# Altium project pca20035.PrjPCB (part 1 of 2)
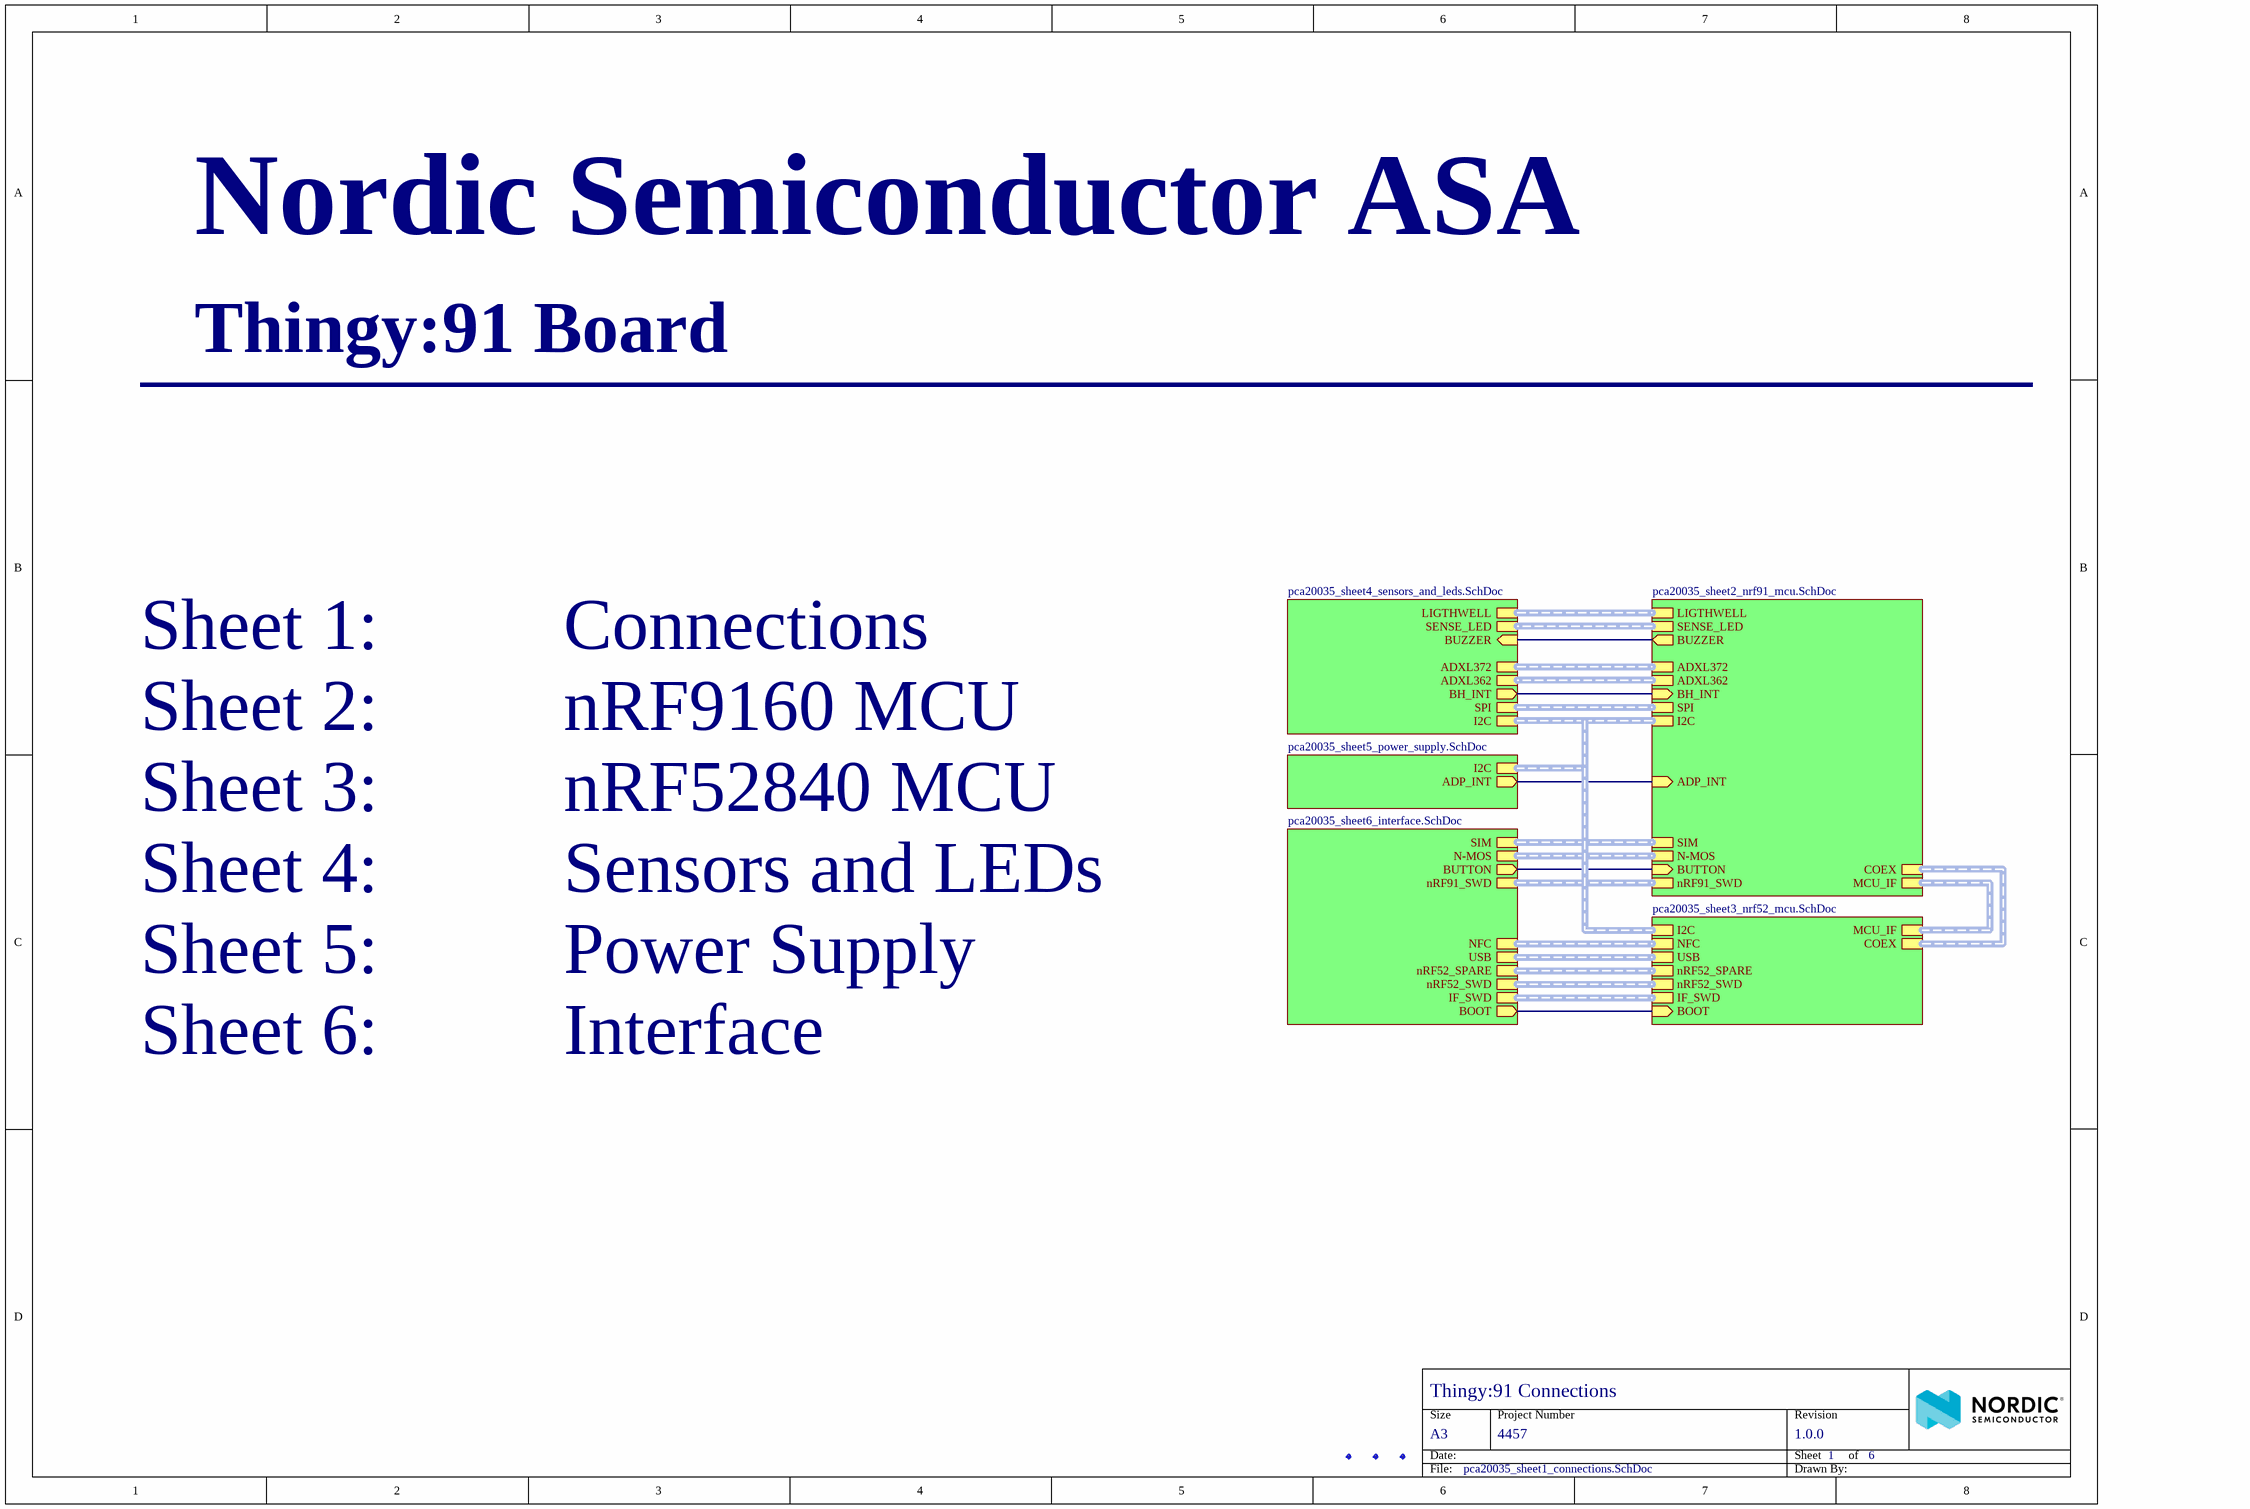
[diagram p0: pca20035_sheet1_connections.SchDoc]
Author: RUBR; BoardThickness: 1.6mm; BoardTitle: Thingy:91 Board; NrOfLayers: 4; Organization: Nordic Semiconductor; PCAName: PCA20035; PCBNumber: 400390; PCBRevision: 0347RUBR; PCBStackup: 4001; ProjectName: nRF91 Thingy; ProjectNumber: 4457; Revision: 1.0.0; SilkscreenColor: White; SoldermaskColor: Blue; SurfaceFinish: ENIG Gold
6 sheets, 236 parts. Net scope: hierarchical (ports join the sheet entries above them; power ports are global).
Board file: 400390.PcbDoc
Sheets:
  pca20035_sheet1_connections.SchDoc
     = pca20035_sheet2_nrf91_mcu.SchDoc
     = pca20035_sheet4_sensors_and_leds.SchDoc
     = pca20035_sheet3_nrf52_mcu.SchDoc
     = pca20035_sheet6_interface.SchDoc
     = pca20035_sheet5_power_supply.SchDoc

## Sheet pca20035_sheet1_connections.SchDoc: Thingy:91 Connections
size A3; Organization: Nordic Semiconductor; DocumentNumber: 1; Revision: 1.0.0; SheetNumber: 1; SheetTotal: 6; Author: RUBR; CompanyName: Nordic Semiconductor; DrawnBy: RUBR; DocumentSize: A3

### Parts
Fid1  Fiducial mark  [Fiducial_Round-Square]  (value not drawn)
Fid2  Fiducial mark  [Fiducial_Round-Square]  (value not drawn)
Fid3  Fiducial mark  [Fiducial_Round-Square]  (value not drawn)

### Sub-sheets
? = pca20035_sheet2_nrf91_mcu.SchDoc: SIM (harness SIM), nRF91_SWD (harness SWD), ADP_INT (in), COEX (harness COEX), BUZZER (out), BH_INT (in), LIGTHWELL (harness LED), MCU_IF (harness MCU_IF), I2C (harness I2C), BUTTON (in), SENSE_LED (harness LED), N-MOS (harness N-MOS), SPI (harness SPI), ADXL372 (harness ADXL), ADXL362 (harness ADXL)
? = pca20035_sheet4_sensors_and_leds.SchDoc: BUZZER (in), I2C (harness I2C), BH_INT (out), LIGTHWELL (harness LED), SENSE_LED (harness LED), SPI (harness SPI), ADXL362 (harness ADXL), ADXL372 (harness ADXL)
? = pca20035_sheet3_nrf52_mcu.SchDoc: USB (harness USB), nRF52_SPARE (harness SPARE), NFC (harness NFC), COEX (harness COEX), IF_SWD (harness IF SWD), I2C (harness I2C), MCU_IF (harness MCU_IF), nRF52_SWD (harness SWD), BOOT (in)
? = pca20035_sheet6_interface.SchDoc: N-MOS (harness N-MOS), NFC (harness NFC), nRF52_SPARE (harness SPARE), SIM (harness SIM), IF_SWD (harness IF SWD), nRF52_SWD (harness SWD), nRF91_SWD (harness SWD), BUTTON (out), USB (harness USB), BOOT (out)
? = pca20035_sheet5_power_supply.SchDoc: I2C (harness I2C), ADP_INT (out)

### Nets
nRF52_P1.13: sheet /BOOT, sheet /BOOT
P0.17/AIN4: sheet /ADP_INT, sheet /ADP_INT
P0.26: sheet /BUTTON, sheet /BUTTON
P0.27: sheet /BH_INT, sheet /BH_INT
P0.28: sheet /BUZZER, sheet /BUZZER

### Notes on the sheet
- Nordic Semiconductor ASA
- ___________________________________________
- Sheet 1:          Connections
- Sheet 2:          nRF9160 MCU
- Sheet 3:          nRF52840 MCU
- Sheet 4:          Sensors and LEDs
- Sheet 5:          Power Supply
- Sheet 6:          Interface

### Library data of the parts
Fid1-Fid3 = Fid-Mark-Round-Square: Artikkelnr Noca: N.A.

## Sheet pca20035_sheet2_nrf91_mcu.SchDoc: Thingy:91 nRF9160 MCU
size A3; Organization: Nordic Semiconductor; DocumentNumber: 2; Revision: 1.0.0; SheetNumber: 2; SheetTotal: 6; Author: RUBR; CompanyName: Nordic Semiconductor; DrawnBy: RUBR; DocumentSize: A3
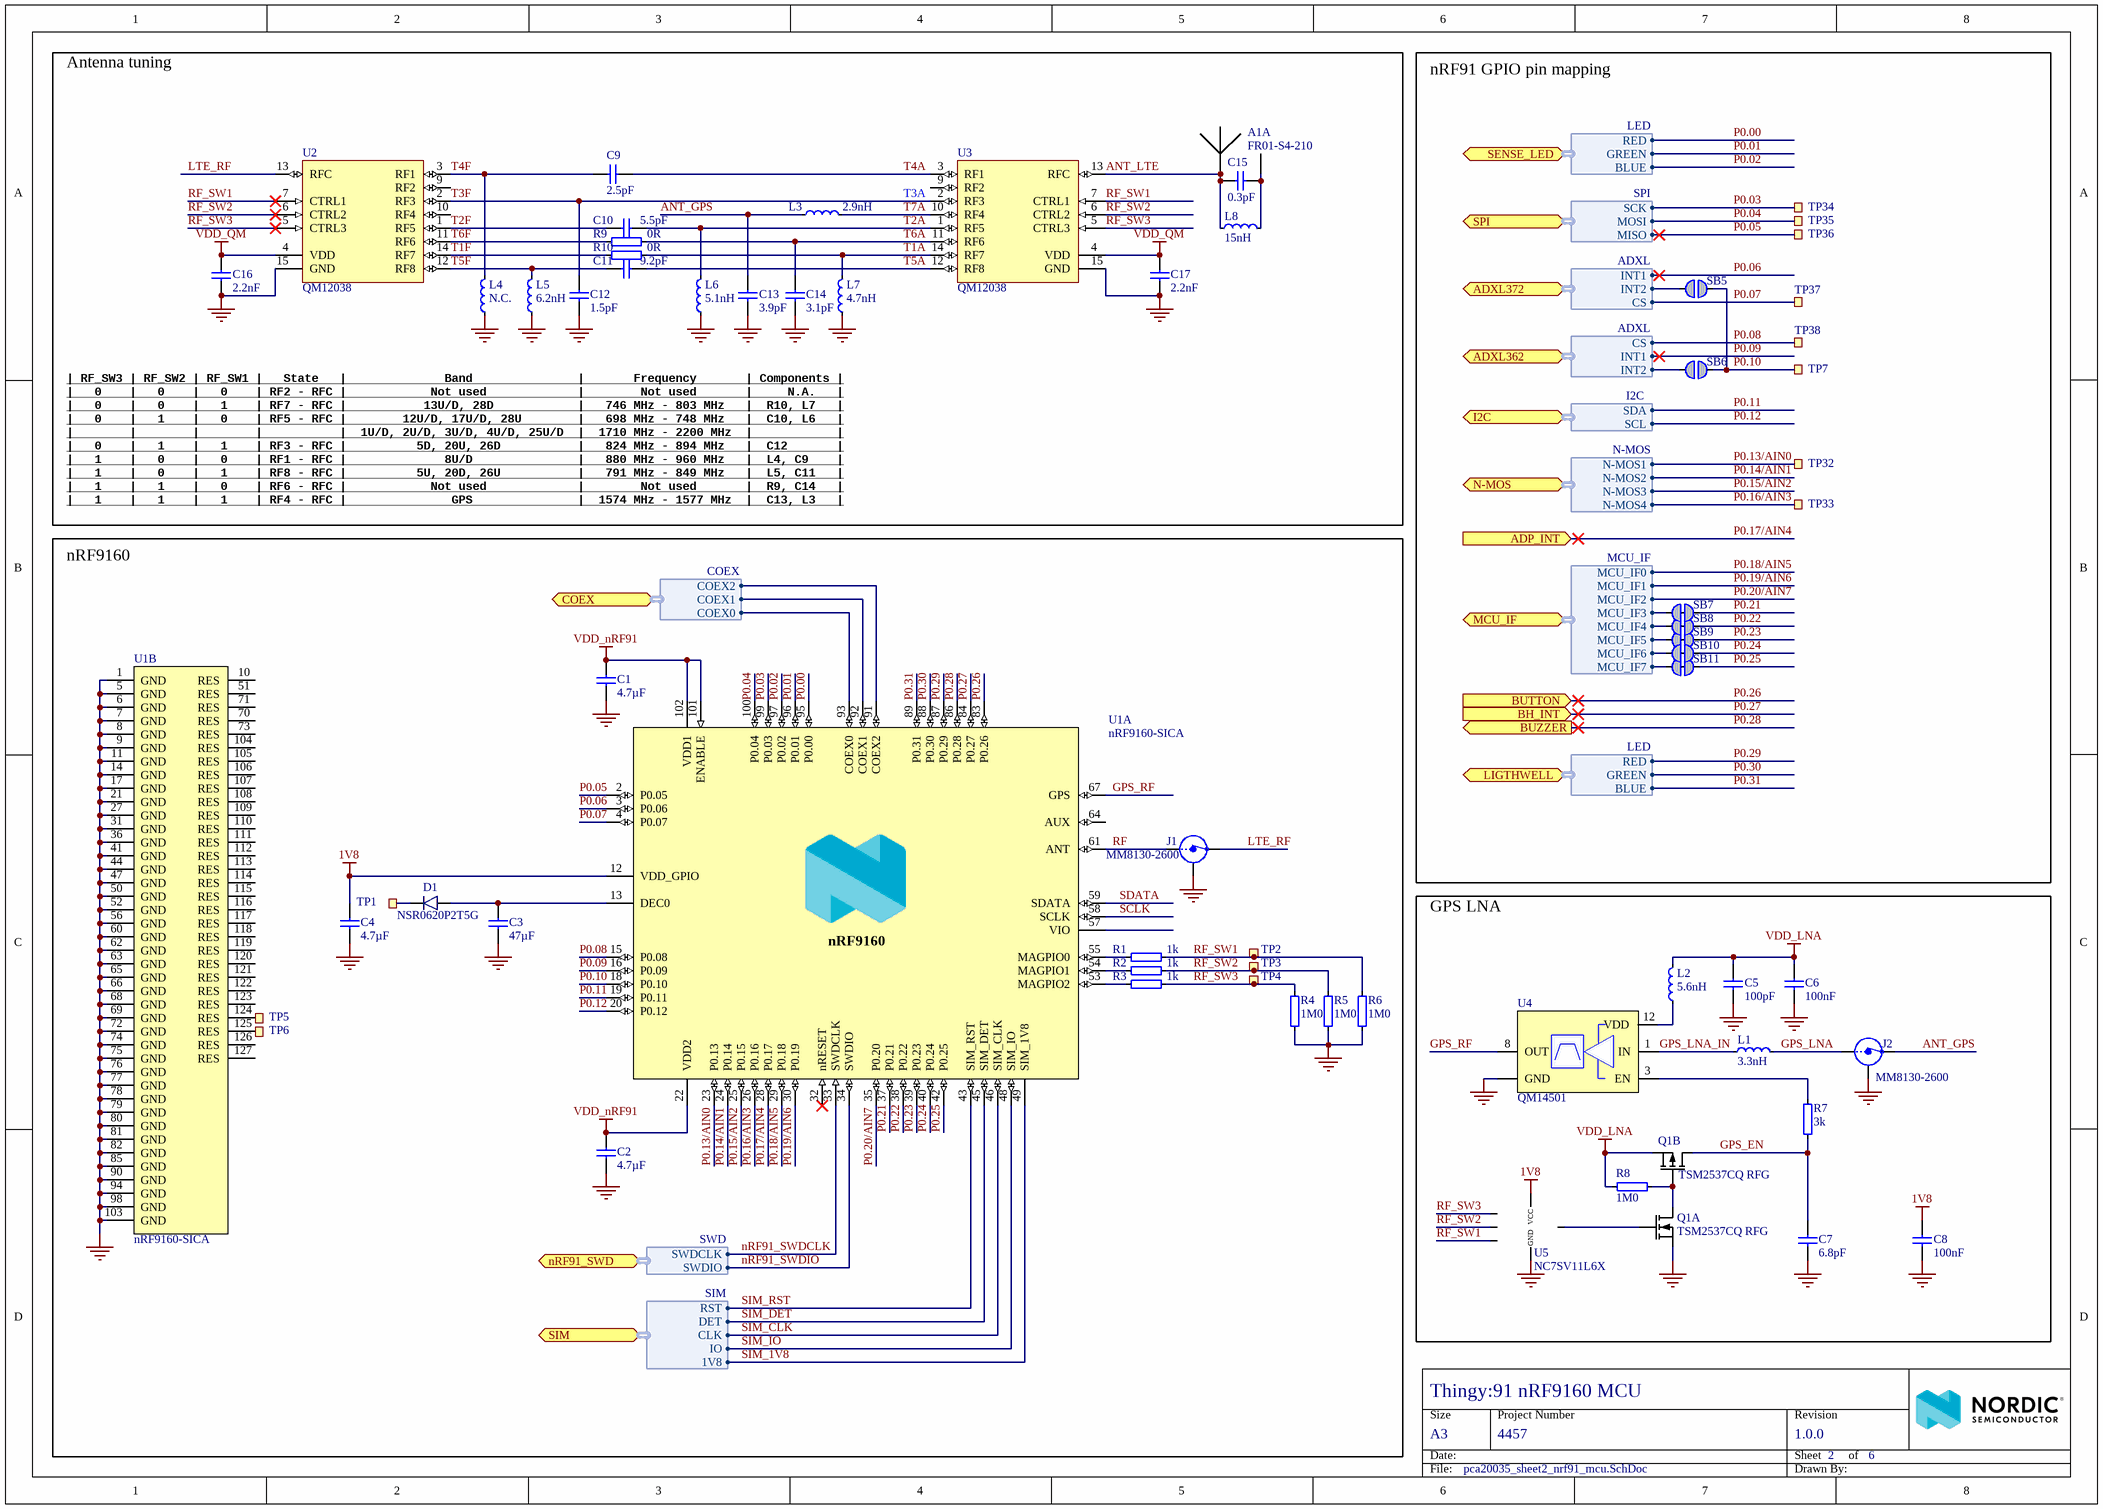
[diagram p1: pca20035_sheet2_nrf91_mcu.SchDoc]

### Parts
A1  FR01-S4-210  [FR01-S4-210_DF]  (part A of 2)
C1  4.7µF  [CAPC1608X06L]
C2  4.7µF  [CAPC1608X06L]
C3  47µF  [CAPC2012X11L]
C4  4.7µF  [CAPC1608X06L]
C5  100pF  [CAPC0603X03L_C]
C6  100nF  [CAPC0603X03L_C]
C7  6.8pF  [CAPC0603X03L_C]
C8  100nF  [CAPC0603X03L_C]
C9  2.5pF  [CAPC0603X03L_C]
C10  5.5pF  [CAPC0603X03L_C]
C11  9.2pF  [CAPC0603X03L_C]
C12  1.5pF  [CAPC0603X03L_C]
C13  3.9pF  [CAPC0603X03L_C]
C14  3.1pF  [CAPC0603X03L_C]
C15  0.3pF  [CAPC1005X04L]
C16  2.2nF  [CAPC0603X03L_C]
C17  2.2nF  [CAPC0603X03L_C]
D1  NSR0620P2T5G  [SODFL100X40-2N]
J1  MM8130-2600  [COAXIAL-SWF]
J2  MM8130-2600  [COAXIAL-SWF]
L1  3.3nH  [INDC0603X03L_C]
L2  5.6nH  [INDC0603X03L_C]
L3  2.9nH  [INDC0603X03L_C]
L4  N.C.  [INDC0603X03L_C]
L5  6.2nH  [INDC0603X03L_C]
L6  5.1nH  [INDC0603X03L_C]
L7  4.7nH  [INDC0603X03L_C]
L8  15nH  [INDC1608X06L]
Q1  TSM2537CQ RFG  [DFN65P200X200X80_HS-6N]  (parts A,B of 2)
R1  1k  [RESC0603X03L_C]
R2  1k  [RESC0603X03L_C]
R3  1k  [RESC0603X03L_C]
R4  1M0  [RESC0603X03L_C]
R5  1M0  [RESC0603X03L_C]
R6  1M0  [RESC0603X03L_C]
R7  3k  [RESC0603X03L_C]
R8  1M0  [RESC0603X03L_C]
R9  0R  [RESC0603X03L_C]
R10  0R  [RESC0603X03L_C]
SB5  Solderbridge  [Solderbridge]  (value not drawn)  (no BOM)
SB6  Solderbridge  [Solderbridge]  (value not drawn)  (no BOM)
SB7  Solderbridge  [Solderbridge_Shorted]  (value not drawn)  (net tie, no BOM)
SB8  Solderbridge  [Solderbridge_Shorted]  (value not drawn)  (net tie, no BOM)
SB9  Solderbridge  [Solderbridge_Shorted]  (value not drawn)  (net tie, no BOM)
SB10  Solderbridge  [Solderbridge_Shorted]  (value not drawn)  (net tie, no BOM)
SB11  Solderbridge  [Solderbridge_Shorted]  (value not drawn)  (net tie, no BOM)
TP1  Ø1.0mm,SMD  [TP_SMD_Ø1.0mm]  (value not drawn)  (no BOM)
TP2  Ø1.0mm,SMD  [TP_SMD_Ø1.0mm]  (value not drawn)  (no BOM)
TP3  Ø1.0mm,SMD  [TP_SMD_Ø1.0mm]  (value not drawn)  (no BOM)
TP4  Ø1.0mm,SMD  [TP_SMD_Ø1.0mm]  (value not drawn)  (no BOM)
TP5  Ø1.0mm,SMD  [TP_SMD_Ø1.0mm]  (value not drawn)  (no BOM)
TP6  Ø1.0mm,SMD  [TP_SMD_Ø1.0mm]  (value not drawn)  (no BOM)
TP7  Ø1.0mm,SMD  [TP_SMD_Ø1.0mm]  (value not drawn)  (no BOM)
TP32  Ø1.5mm,SMD  [TP_SMD_Ø1.5mm]  (value not drawn)  (no BOM)
TP33  Ø1.5mm,SMD  [TP_SMD_Ø1.5mm]  (value not drawn)  (no BOM)
TP34  Ø1.0mm,SMD  [TP_SMD_Ø1.0mm]  (value not drawn)  (no BOM)
TP35  Ø1.0mm,SMD  [TP_SMD_Ø1.0mm]  (value not drawn)  (no BOM)
TP36  Ø1.0mm,SMD  [TP_SMD_Ø1.0mm]  (value not drawn)  (no BOM)
TP37  Ø1.0mm,SMD  [TP_SMD_Ø1.0mm]  (value not drawn)  (no BOM)
TP38  Ø1.0mm,SMD  [TP_SMD_Ø1.0mm]  (value not drawn)  (no BOM)
U1  nRF9160-SICA  [LGA50P1600X1050X104-161N]  (parts A,B of 2)
U2  QM12038  [UFQFN40P200X200X65_HS-15N]
U3  QM12038  [UFQFN40P200X200X65_HS-15N]
U4  QM14501  [QM14501]
U5  NC7SV11L6X  [DFN1410-6N]

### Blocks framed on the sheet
Antenna tuning: A1 C9-C17 L3-L8 R9 R10 U2 U3
nRF91 GPIO pin mapping: SB5-SB11 TP7 TP32-TP38
nRF9160: C1-C4 D1 J1 R1-R6 TP1-TP6 U1
GPS LNA: C5-C8 J2 L1 L2 Q1 R7 R8 U4 U5

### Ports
ADP_INT (in), ADXL362 (bidir, harness ADXL), ADXL372 (bidir, harness ADXL), BH_INT (in), BUTTON (in), BUZZER (out), COEX (bidir, harness COEX), I2C (bidir, harness I2C), LIGTHWELL (bidir, harness LED), MCU_IF (bidir, harness MCU_IF), N-MOS (bidir, harness N-MOS), nRF91_SWD (bidir, harness SWD), SENSE_LED (bidir, harness LED), SIM (bidir, harness SIM), SPI (bidir, harness SPI)

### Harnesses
SWD: SWDIO, SWDCLK
I2C: SDA, SCL
MCU_IF: MCU_IF0, MCU_IF1, MCU_IF2, MCU_IF3, MCU_IF4, MCU_IF5, MCU_IF6, MCU_IF7
LED: BLUE, GREEN, RED
SIM: DET, RST, CLK, IO, 1V8
COEX: COEX2, COEX1, COEX0
SPI: MISO, MOSI, SCK
N-MOS: N-MOS1, N-MOS2, N-MOS3, N-MOS4
ADXL: CS, INT2, INT1

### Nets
1V8: C4.1 C8.2 U1.12(VDD_GPIO) U5.5(VCC)
GND: C1.1 C2.1 C3.2 C4.2 C5.1 C6.1 C7.1 C8.1 C12.1 C13.1 C14.1 C16.1 C17.1 J1.2(Shield) J2.2(Shield) L4.1 L5.1 L6.1 L7.1 Q1.1(S1) R4.1 R5.1 R6.1 U1.1(GND) U1.5(GND) U1.6(GND) U1.7(GND) U1.8(GND) U1.9(GND) U1.11(GND) U1.14(GND) U1.17(GND) U1.21(GND) U1.27(GND) U1.31(GND) U1.36(GND) U1.41(GND) U1.44(GND) U1.47(GND) U1.50(GND) U1.52(GND) U1.56(GND) U1.60(GND) U1.62(GND) U1.63(GND) U1.65(GND) U1.66(GND) U1.68(GND) U1.69(GND) U1.72(GND) U1.74(GND) U1.75(GND) U1.76(GND) U1.77(GND) U1.78(GND) U1.79(GND) U1.80(GND) U1.81(GND) U1.82(GND) U1.85(GND) U1.90(GND) U1.94(GND) U1.98(GND) U1.103(GND) U2.15(GND) U3.15(GND) U4.2(GND) U4.4(GND) U4.5(GND) U4.6(GND) U4.7(GND) U4.9(GND) U4.10(GND) U4.11(GND) U5.2(GND)
VDD_LNA: C5.2 C6.2 L2.2 Q1.4(S2) R8.1
VDD_nRF91: C1.2 C2.2 U1.22(VDD2) U1.101(ENABLE) U1.102(VDD1)
VDD_QM: C16.2 C17.2 U2.4(VDD) U3.4(VDD)
ANT_GPS: C13.2 J2.3(OUT) L3.1
ANT_LTE: A1.1(Feed_A) C15.1 L8.1 U3.13(RFC)
GPS_EN: C7.2 Q1.3(D2) R7.2
GPS_LNA: J2.1(IN) L1.2
GPS_LNA_IN: L1.1 U4.1(IN)
GPS_RF: U1.67(GPS) U4.8(OUT)
LTE_RF: J1.3(OUT) U2.13(RFC)
nRF52_P0.19: SB10.1 ; port MCU_IF.MCU_IF6
nRF52_P0.21: SB7.1 ; port MCU_IF.MCU_IF3
nRF52_P0.22: SB11.1 ; port MCU_IF.MCU_IF7
nRF52_P0.25: SB9.1 ; port MCU_IF.MCU_IF5
nRF52_P1.00: SB8.1 ; port MCU_IF.MCU_IF4
nRF52_P1.01: U1.91(COEX2) ; port COEX.COEX2
nRF52_P1.04: U1.92(COEX1) ; port COEX.COEX1
nRF52_P1.07: U1.93(COEX0) ; port COEX.COEX0
nRF91_SWDCLK: U1.33(SWDCLK) ; port nRF91_SWD.SWDCLK
nRF91_SWDIO: U1.34(SWDIO) ; port nRF91_SWD.SWDIO
P0.00: U1.95(P0.00) ; port SENSE_LED.RED
P0.01: U1.96(P0.01) ; port SENSE_LED.GREEN
P0.02: U1.97(P0.02) ; port SENSE_LED.BLUE
P0.03: TP34.1 U1.99(P0.03) ; port SPI.SCK
P0.04: TP35.1 U1.100(P0.04) ; port SPI.MOSI
P0.05: TP36.1 U1.2(P0.05) ; port SPI.MISO
P0.06: U1.3(P0.06) ; port ADXL372.INT1
P0.07: TP37.1 U1.4(P0.07) ; port ADXL372.CS
P0.08: TP38.1 U1.15(P0.08) ; port ADXL362.CS
P0.09: U1.16(P0.09) ; port ADXL362.INT1
P0.10: SB5.1 SB6.1 TP7.1 U1.18(P0.10)
P0.11: U1.19(P0.11) ; port I2C.SDA  [project net nRF52_P1.08]
P0.12: U1.20(P0.12) ; port I2C.SCL  [project net nRF52_P1.09]
P0.13/AIN0: TP32.1 U1.23(P0.13) ; port N-MOS.N-MOS1
P0.14/AIN1: U1.24(P0.14) ; port N-MOS.N-MOS2
P0.15/AIN2: U1.25(P0.15) ; port N-MOS.N-MOS3
P0.16/AIN3: TP33.1 U1.26(P0.16) ; port N-MOS.N-MOS4
P0.17/AIN4: U1.28(P0.17) ; port ADP_INT
P0.18/AIN5: U1.29(P0.18) ; port MCU_IF.MCU_IF0  [project net nRF52_P0.11]
P0.19/AIN6: U1.30(P0.19) ; port MCU_IF.MCU_IF1  [project net nRF52_P0.15]
P0.20/AIN7: U1.35(P0.20) ; port MCU_IF.MCU_IF2  [project net nRF52_P0.20]
P0.21: SB7.2 U1.37(P0.21)
P0.22: SB8.2 U1.38(P0.22)
P0.23: SB9.2 U1.39(P0.23)
P0.24: SB10.2 U1.40(P0.24)
P0.25: SB11.2 U1.42(P0.25)
P0.26: U1.83(P0.26) ; port BUTTON
P0.27: U1.84(P0.27) ; port BH_INT
P0.28: U1.86(P0.28) ; port BUZZER
P0.29: U1.87(P0.29) ; port LIGTHWELL.RED
P0.30: U1.88(P0.30) ; port LIGTHWELL.GREEN
P0.31: U1.89(P0.31) ; port LIGTHWELL.BLUE
RF: J1.1(IN) U1.61(ANT)
RF_SW1: R1.2 R6.2 TP2.1 U2.7(CTRL1) U3.7(CTRL1) U5.6(C)
RF_SW2: R2.2 R5.2 TP3.1 U2.6(CTRL2) U3.6(CTRL2) U5.3(B)
RF_SW3: R3.2 R4.2 TP4.1 U2.5(CTRL3) U3.5(CTRL3) U5.1(A)
SCLK: U1.58(SCLK)
SDATA: U1.59(SDATA)
SIM_1V8: U1.49(SIM_1V8) ; port SIM.1V8
SIM_CLK: U1.46(SIM_CLK) ; port SIM.CLK
SIM_DET: U1.45(SIM_DET) ; port SIM.DET
SIM_IO: U1.48(SIM_IO) ; port SIM.IO
SIM_RST: U1.43(SIM_RST) ; port SIM.RST
T1A: L7.2 R10.1 U3.14(RF7)
T1F: R10.2 U2.14(RF7)
T2A: C10.1 L6.2 U3.1(RF5)
T2F: C10.2 U2.1(RF5)
T3F: C12.2 U2.2(RF3) U3.2(RF3)
T4A: C9.1 U3.3(RF1)
T4F: C9.2 L4.2 U2.3(RF1)
T5A: C11.1 U3.12(RF8)
T5F: C11.2 L5.2 U2.12(RF8)
T6A: C14.2 R9.1 U3.11(RF6)
T6F: R9.2 U2.11(RF6)
T7A: L3.2 U3.10(RF4)
NetA1_2: A1.2(Tuning_A) C15.2 L8.2
NetC3_1: C3.1 D1.2(A) U1.13(DEC0)
NetD1_1: D1.1(C) TP1.1
NetL2_1: L2.1 U4.12(VDD)
NetQ1_2: Q1.2(G1) U5.4(Y)
NetQ1_5: Q1.5(G2) Q1.6(D1) R8.2
NetR1_1: R1.1 U1.55(MAGPIO0)
NetR2_1: R2.1 U1.54(MAGPIO1)
NetR3_1: R3.1 U1.53(MAGPIO2)
NetR7_1: R7.1 U4.3(EN)
NetSB5_2: SB5.2 ; port ADXL372.INT2
NetSB6_2: SB6.2 ; port ADXL362.INT2
NetTP5_1: TP5.1 U1.124(RES)
NetTP6_1: TP6.1 U1.125(RES)

Not connected (* = marked no-connect by the designer): U1 10(RES) 32(nRESET)* 51(RES) 57(VIO) 64(AUX) 70(RES) 71(RES) 73(RES) 104(RES) 105(RES) 106(RES) 107(RES) 108(RES) 109(RES) 110(RES) 111(RES) 112(RES) 113(RES) 114(RES) 115(RES) 116(RES) 117(RES) 118(RES) 119(RES) 120(RES) 121(RES) 122(RES) 123(RES) 126(RES) 127(RES); U2 8(NC) 9(RF2) 10(RF4); U3 8(NC) 9(RF2)

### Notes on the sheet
- (near U3) T3A
- | RF_SW3 | RF_SW2 | RF_SW1 |   State   |              Band               |       Frequency       | Components |
  |   0    |   0    |   0    | RF2 - RFC |            Not used             |        Not used       |     N.A.   |
  |   0    |   0    |   1    | RF7 - RFC |           13U/D, 28D            |   746 MHz - 803 MHz   |  R10, L7   |
  |   0    |   1    |   0    | RF5 - RFC |        12U/D, 17U/D, 28U        |   698 MHz - 748 MHz   |  C10, L6   |
  |        |        |        |           |  1U/D, 2U/D, 3U/D, 4U/D, 25U/D  |  1710 MHz - 2200 MHz  |            |
  |   0    |   1    |   1    | RF3 - RFC |          5D, 20U, 26D           |   824 MHz - 894 MHz   |  C12       |
  |   1    |   0    |   0    | RF1 - RFC |              8U/D               |   880 MHz - 960 MHz   |  L4, C9    |
  |   1    |   0    |   1    | RF8 - RFC |          5U, 20D, 26U           |   791 MHz - 849 MHz   |  L5, C11   |
  |   1    |   1    |   0    | RF6 - RFC |            Not used             |        Not used       |  R9, C14   |
  |   1    |   1    |   1    | RF4 - RFC |               GPS               |  1574 MHz - 1577 MHz  |  C13, L3   |

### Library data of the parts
A1 = FR01-S4-210-D: Mobile IoT LTE Multi-Band Antenna; Manufacturer: Fractus Antennas; Part number IPS: 80000001819; Artikkelnr Noca: N.A.
C1 C2 C4 = C0603-4µ7: Capacitor, X5R, ±10%; Part number IPS: 00000007783; Note: 6.3V; Artikkelnr Noca: 20069060
C3 = C0805-47µ: Capacitor, X5R, ±20%, 6.3V; Manufacturer: Taiyo Yuden; Manufacturer Part Number: JMK212BJ476MG-T; Artikkelnr Noca: N.A.
C5 = C0201-100p: Capacitor, NP0, ±2%, 25V; Part number IPS: 00000007853; Artikkelnr Noca: N.A.
C6 C8 = C0201-100n: Capacitor, X5R, ±10%; Part number IPS: 00000001248; Note: 16V; Artikkelnr Noca: N.A.
C7 = C0201-6.8p: Capacitor, NP0, ±0.25pF, 25V; Part number IPS: 00000005766; Artikkelnr Noca: N.A.
C9 = C0201-2.5p-HQ-Murata: Capacitor, NP0, ±0.05pF, 25V; Manufacturer: Murata; Manufacturer Part Number: GJM0333C1E2R5WB01; Part number IPS: 00000001771; Artikkelnr Noca: N.A.
C10 = C0201-5.5p-HQ-Murata: Capacitor, NP0, ±0.05pF, 25V; Manufacturer: Murata; Manufacturer Part Number: GJM0332C1H5R5WB01; Part number IPS: 00000001772; Artikkelnr Noca: N.A.
C11 = C0201-9.2p-HQ-Murata: Capacitor, NP0, ±0.05pF, 25V; Manufacturer: Murata; Manufacturer Part Number: GJM0332C1E9R2WB01; Artikkelnr Noca: N.A.
C12 = C0201-1.5p-HQ-Murata: Capacitor, NP0, ±0.05pF, 25V; Manufacturer: Murata; Manufacturer Part Number: GJM0334C1E1R5WB01; Part number IPS: 00000001774; Artikkelnr Noca: N.A.
C13 = C0201-3.9p-HQ-Murata: Capacitor, NP0, ±0.05pF, 25V; Manufacturer: Murata; Manufacturer Part Number: GJM0333C1E3R9WB01; Artikkelnr Noca: N.A.
C14 = C0201-3.1p-HQ-Murata: Capacitor, NP0, ±0.05pF, 25V; Manufacturer: Murata; Manufacturer Part Number: GJM0335C1E3R1WB01; Part number IPS: 00000001776; Artikkelnr Noca: N.A.
C15 = C0402-0.3p-HQ-Murata: Capacitor, NP0, ±0.05pF, 50V; Manufacturer: Murata; Manufacturer Part Number: GJM1555C1HR30WB01D; Part number IPS: 00000001777; Artikkelnr Noca: N.A.
C16 C17 = C0201-2n2: Capacitor, X7R, ±10%, 10V; Part number IPS: 00000001778; Artikkelnr Noca: N.A.
D1 = NSR0620P2T5G: 20V schottky barrier diode, Vf 350 mV @ 100 mA, Ir 2.0 µA @ 10 V, If 500 mA; Manufacturer: ON Semiconductor; Part number IPS: 00000009952; Artikkelnr Noca: 10029169
J1 J2 = MM8130-2600: Coaxial Connector with Switch; Manufacturer: Murata; Part number IPS: 00000009955; Artikkelnr Noca: 55029011
L1 = L0201-3n3-Wirewound-Murata: Inductor, 520mA, ±0.2nH, 110mOhm, Q=47; Manufacturer: Murata; Manufacturer Part Number: LQW03AW3N3C00; Part number IPS: 00000001786; Note: -55°C ~ 125°C; Artikkelnr Noca: N.A.
L2 = L0201-5n6: Inductor, 350mA, ±3%; Manufacturer: Murata; Manufacturer Part Number: LQP03TN5N6H02D; Part number IPS: 00000001416; Artikkelnr Noca: N.A.
L3 = L0201-2n9-Wirewound-Murata: Inductor, 540mA, ±0.2nH, 100mOhm, Q=41; Manufacturer: Murata; Manufacturer Part Number: LQW03AW2N9C00; Part number IPS: 00000001787; Note: -55°C ~ 125°C; Artikkelnr Noca: N.A.
L4 = L0201-N.C.: Not mounted; Assembly: Not mounted; Artikkelnr Noca: N.A.
L5 = L0201-6n2-Wirewound-Murata: Inductor, 360mA, ±5%, 220mOhm, Q=39; Manufacturer: Murata; Manufacturer Part Number: LQW03AW6N2J00; Note: -55°C ~ 125°C; Artikkelnr Noca: N.A.
L6 = L0201-5n1-Wirewound-Murata: Inductor, 480mA, ±5%, 140mOhm, Q=45; Manufacturer: Murata; Manufacturer Part Number: LQW03AW5N1J00; Part number IPS: 00000001789; Note: -55°C ~ 125°C; Artikkelnr Noca: N.A.
L7 = L0201-4n7-Wirewound-Murata: Inductor, 620mA, ±5%, 90mOhm, Q=45; Manufacturer: Murata; Manufacturer Part Number: LQW03AW4N7J00; Part number IPS: 00000001790; Note: -55°C ~ 125°C; Artikkelnr Noca: N.A.
L8 = L0603-15n-HQ-Murata: Inductor, 1400mA, ±2%, 75mOhm; Manufacturer: Murata; Manufacturer Part Number: LQW18AN15NG80D; Part number IPS: 00000001791; Note: -55°C ~ 125°C; Artikkelnr Noca: N.A.
Q1 = TSM2537CQ RFG: Dual N & P Ch MOFET, 11.6A/9A, 90mOhm max, 6.25W; Manufacturer: Taiwan Semiconductor; Part number IPS: 00000001702; Artikkelnr Noca: N.A.
R1-R3 = R0201-1k0: Resistor, ±1%, 0.05W; Part number IPS: 00000005786; Note: Chip Res 1%; Artikkelnr Noca: N.A.
R4-R6 R8 = R0201-1M0: Resistor, ±1%, 0.05W; Part number IPS: 00000001418; Note: Chip Res 1%; Artikkelnr Noca: N.A.
R7 = R0201-3k0: Resistor, ±1%, 0.05W; Part number IPS: 00000001688; Note: Chip Res 1%; Artikkelnr Noca: N.A.
R9 R10 = R0201-0R: Resistor, ±5%, 0.05W; Part number IPS: 00000003245; Note: Chip Res 5%; Artikkelnr Noca: N.A.
SB5 SB6 = Solderbridge: Artikkelnr Noca: N.A.
SB7-SB11 = Solderbridge Shorted: Shorted Solderbridge; Artikkelnr Noca: N.A.
TP1-TP7 TP34-TP38 = TP_SMD_Ø1.0MM: 1.0mm circular SMD testpad; Manufacturer: Nordic Semiconductor; Artikkelnr Noca: N.A.
TP32 TP33 = TP_SMD_Ø1.5MM: 1.0mm circular SMD testpad; Manufacturer: Nordic Semiconductor; Artikkelnr Noca: N.A.
U1 = nRF9160-SICA: Low power System-in-Package with integrated LTE-M/NB-IoT modem and GPS; Manufacturer: Nordic Semiconductor; Artikkelnr Noca: N.A.
U2 U3 = QM12038: SP8T Switch For 3G/4G Applications; Manufacturer: Qorvo; Part number IPS: 80000001821; Artikkelnr Noca: N.A.
U4 = QM14501: GPS, GLONASS, and BeiDou Low Noise Amplifier With Integrated Output SAW Filter, 1.55 to 1.61 GHz, 13.5 dB; Manufacturer: Qorvo; Part number IPS: 80000001649; Artikkelnr Noca: N.A.
U5 = NC7SV11L6X: Single 3-input AND gate; Manufacturer: ON Semiconductor; Part number IPS: 00000001709; Artikkelnr Noca: N.A.

## Sheet pca20035_sheet4_sensors_and_leds.SchDoc: Thingy:91 Sensors and LEDs
size A3; Organization: Nordic Semiconductor; DocumentNumber: 4; Revision: 1.0.0; SheetNumber: 4; SheetTotal: 6; Author: RUBR; CompanyName: Nordic Semiconductor; DrawnBy: RUBR; DocumentSize: A3
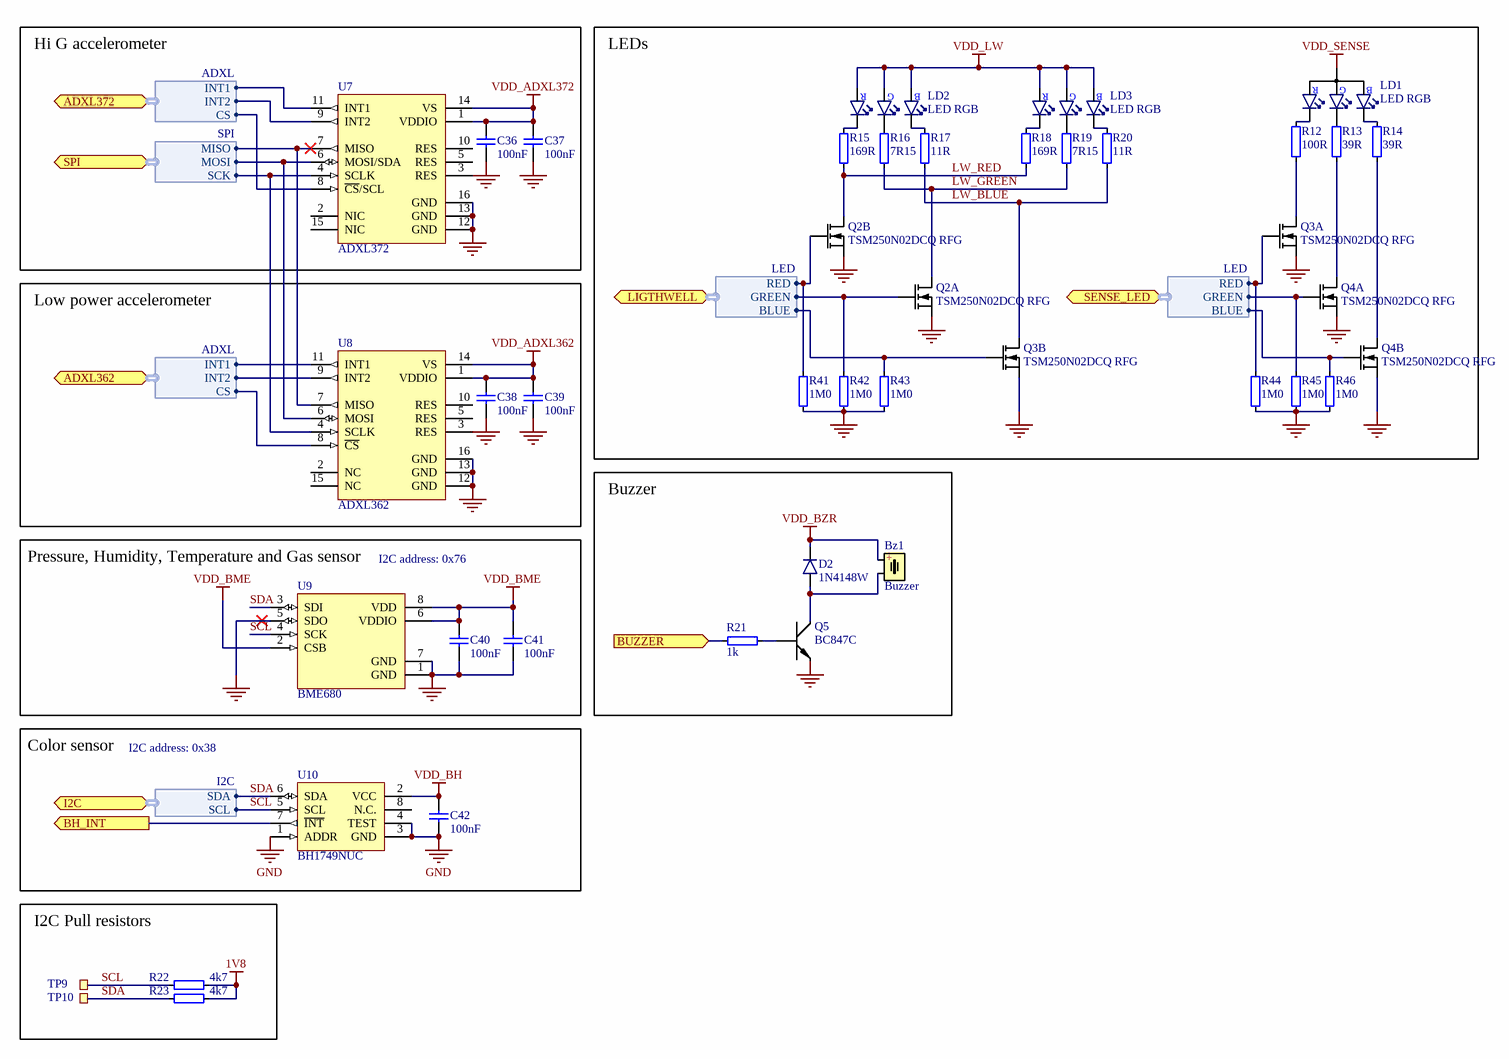
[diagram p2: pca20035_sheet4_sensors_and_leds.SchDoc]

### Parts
Bz1  Buzzer  [Buzzer_SMD_7.5x7.5]
C36  100nF  [CAPC0603X03L_C]
C37  100nF  [CAPC0603X03L_C]
C38  100nF  [CAPC0603X03L_C]
C39  100nF  [CAPC0603X03L_C]
C40  100nF  [CAPC0603X03L_C]
C41  100nF  [CAPC0603X03L_C]
C42  100nF  [CAPC0603X03L_C]
D2  1N4148W  [SOD-123-DIODE]
LD1  LED RGB  [LED_RGB_0606]
LD2  LED RGB  [MSL0104]
LD3  LED RGB  [MSL0104]
Q2  TSM250N02DCQ RFG  [DFN65P200X200X80_HS-6N]  (parts A,B of 2)
Q3  TSM250N02DCQ RFG  [DFN65P200X200X80_HS-6N]  (parts A,B of 2)
Q4  TSM250N02DCQ RFG  [DFN65P200X200X80_HS-6N]  (parts A,B of 2)
Q5  BC847C  [SOT-23a]
R12  100R  [RESC0603X03L_C]
R13  39R  [RESC0603X03L_C]
R14  39R  [RESC0603X03L_C]
R15  169R  [RESC1005X04L]
R16  7R15  [RESC1005X04L]
R17  11R  [RESC1005X04L]
R18  169R  [RESC1005X04L]
R19  7R15  [RESC1005X04L]
R20  11R  [RESC1005X04L]
R21  1k  [RESC0603X03L_C]
R22  4k7  [RESC0603X03L_C]
R23  4k7  [RESC0603X03L_C]
R41  1M0  [RESC0603X03L_C]
R42  1M0  [RESC0603X03L_C]
R43  1M0  [RESC0603X03L_C]
R44  1M0  [RESC0603X03L_C]
R45  1M0  [RESC0603X03L_C]
R46  1M0  [RESC0603X03L_C]
TP9  Ø1.5mm,SMD  [TP_SMD_Ø1.5mm]  (value not drawn)  (no BOM)
TP10  Ø1.5mm,SMD  [TP_SMD_Ø1.5mm]  (value not drawn)  (no BOM)
U7  ADXL372  [LGA50P322X300X114-16N]
U8  ADXL362  [LGA50P322X300X114-16N]
U9  BME680  [BME680]
U10  BH1749NUC  [WSON50P210X210X60_HS-9N]

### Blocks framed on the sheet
Hi G accelerometer: C36 C37 U7
LEDs: LD1-LD3 Q2-Q4 R12-R20 R41-R46
Low power accelerometer: C38 C39 U8
Buzzer: Bz1 D2 Q5 R21
Pressure, Humidity, Temperature and Gas sensor: C40 C41 U9
Color sensor: C42 U10
I2C Pull resistors: R22 R23 TP9 TP10

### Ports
ADXL362 (bidir, harness ADXL), ADXL372 (bidir, harness ADXL), BH_INT (out), BUZZER (in), I2C (bidir, harness I2C), LIGTHWELL (bidir, harness LED), SENSE_LED (bidir, harness LED), SPI (bidir, harness SPI)

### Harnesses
I2C: SDA, SCL
LED: BLUE, GREEN, RED
SPI: MISO, MOSI, SCK
ADXL: CS, INT2, INT1

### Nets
1V8: R22.1 R23.1
GND: C36.1 C37.1 C38.1 C39.1 C40.1 C41.1 C42.1 Q2.1(S1) Q2.4(S2) Q3.1(S1) Q3.4(S2) Q4.1(S1) Q4.4(S2) Q5.2(E) R41.1 R42.1 R43.1 R44.1 R45.1 R46.1 U7.12(GND) U7.13(GND) U7.16(GND) U8.12(GND) U8.13(GND) U8.16(GND) U9.1(GND) U9.5(SDO) U9.7(GND) U10.1(ADDR) U10.3(GND) U10.4(TEST) U10.9(GND)
VDD_ADXL362: C38.2 C39.2 U8.1(VDDIO) U8.14(VS)
VDD_ADXL372: C36.2 C37.2 U7.1(VDDIO) U7.14(VS)
VDD_BH: C42.2 U10.2(VCC)
VDD_BME: C40.2 C41.2 U9.2(CSB) U9.6(VDDIO) U9.8(VDD)
VDD_BZR: Bz1.1 D2.1(C)
VDD_LW: LD2.1(A_RED) LD2.2(A_GREEN) LD2.6(A_BLUE) LD3.1(A_RED) LD3.2(A_GREEN) LD3.6(A_BLUE)
VDD_SENSE: LD1.4(A)
LW_BLUE: Q3.3(D2) R17.1 R20.1
LW_GREEN: Q2.6(D1) R16.1 R19.1
LW_RED: Q2.3(D2) R15.1 R18.1
P0.00: Q3.2(G1) R44.2 ; port SENSE_LED.RED
P0.01: Q4.2(G1) R45.2 ; port SENSE_LED.GREEN
P0.02: Q4.5(G2) R46.2 ; port SENSE_LED.BLUE
P0.03: U7.4(SCLK) U8.4(SCLK) ; port SPI.SCK
P0.04: U7.6(MOSI/SDA) U8.6(MOSI) ; port SPI.MOSI
P0.05: U7.7(MISO) U8.7(MISO) ; port SPI.MISO
P0.06: U7.11(INT1) ; port ADXL372.INT1
P0.07: U7.8(~{CS}/SCL) ; port ADXL372.CS
P0.08: U8.8(~{CS}) ; port ADXL362.CS
P0.09: U8.11(INT1) ; port ADXL362.INT1
P0.27: U10.7(~{INT}) ; port BH_INT
P0.28: R21.2 ; port BUZZER
P0.29: Q2.5(G2) R41.2 ; port LIGTHWELL.RED
P0.30: Q2.2(G1) R42.2 ; port LIGTHWELL.GREEN
P0.31: Q3.5(G2) R43.2 ; port LIGTHWELL.BLUE
SCL: R22.2 TP9.1 U9.4(SCK) U10.5(SCL) ; port I2C.SCL  [project net nRF52_P1.09]
SDA: R23.2 TP10.1 U9.3(SDI) U10.6(SDA) ; port I2C.SDA  [project net nRF52_P1.08]
NetBz1_2: Bz1.2 D2.2(A) Q5.3(C)
NetLD1_1: LD1.1(C_RED) R12.2
NetLD1_2: LD1.2(C_GREEN) R13.2
NetLD1_3: LD1.3(C_BLUE) R14.2
NetLD2_3: LD2.3(C_GREEN) R16.2
NetLD2_4: LD2.4(C_RED) R15.2
NetLD2_5: LD2.5(C_BLUE) R17.2
NetLD3_3: LD3.3(C_GREEN) R19.2
NetLD3_4: LD3.4(C_RED) R18.2
NetLD3_5: LD3.5(C_BLUE) R20.2
NetQ3_6: Q3.6(D1) R12.1
NetQ4_3: Q4.3(D2) R14.1
NetQ4_6: Q4.6(D1) R13.1
NetQ5_1: Q5.1(B) R21.1
NetSB5_2: U7.9(INT2) ; port ADXL372.INT2
NetSB6_2: U8.9(INT2) ; port ADXL362.INT2

Not connected (* = marked no-connect by the designer): U7 2(NIC) 3(RES) 5(RES) 10(RES) 15(NIC); U8 2(NC) 3(RES) 5(RES) 10(RES) 15(NC); U10 8(N.C.)

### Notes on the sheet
- (near U9) I2C address: 0x76
- I2C address: 0x38

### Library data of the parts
Bz1 = AST7525MATRQ: Buzzer Transducer, 3.6V 100mA 2.7kHz 85dB @ 3.6V, SMD; Manufacturer: Mallory; Part number IPS: 00000001770; Artikkelnr Noca: N.A.
C36-C42 = C0201-100n: as C6 on sheet pca20035_sheet2_nrf91_mcu
D2 = 1N4148W: 1N4148, Small Signal Fast Switching Diode; Manufacturer: Vishay; Manufacturer Part Number: 1N4148W-E3-08; Part number IPS: 00000001783; Artikkelnr Noca: N.A.
LD1 = LTST-C19HE1WT: RGB LED 1.60 mm x 1.60 mm SMD; Manufacturer: Lite-On Inc; Part number IPS: 00000007798; Artikkelnr Noca: N.A.
LD2 LD3 = MSL0104RGBU1: High brightness, side view RGB LED; Manufacturer: ROHM; Part number IPS: 00000007799; Artikkelnr Noca: N.A.
Q2-Q4 = TSM250N02DCQ RFG: Dual N Ch MOFET, 5.8A, 55mOhm max, 620mW; Manufacturer: Taiwan Semiconductor; Part number IPS: 00000001703; Artikkelnr Noca: N.A.
Q5 = BC847C: BC847C, NPN Silicon transistor; Manufacturer: NXP; Part number IPS: 00000001793; Note: NPN Epitaxial Silicon Transistor; Artikkelnr Noca: 35019020
R12 = R0201-100: Resistor, ±1%, 0.05W; Part number IPS: 00000001794; Note: Chip Res 1%; Artikkelnr Noca: N.A.
R13 R14 = R0201-39R: Resistor, ±1%, 0.05W; Part number IPS: 00000001704; Note: Chip Res 1%; Artikkelnr Noca: N.A.
R15 R18 = R0402-169: Resistor, ±1%, 0.063W; Part number IPS: 00000007805; Note: Chip Res 1%; Artikkelnr Noca: N.A.
R16 R19 = R0402-7R15: Resistor, ±1%, 0.063W; Part number IPS: 00000007806; Note: Chip Res 1%; Artikkelnr Noca: N.A.
R17 R20 = R0402-11R: Resistor, ±1%, 0.063W; Part number IPS: 00000007807; Note: Chip Res 1%; Artikkelnr Noca: N.A.
R21 = R0201-1k0: as R1 on sheet pca20035_sheet2_nrf91_mcu
R22 R23 = R0201-4k7: Resistor, ±1%, 0.05W; Part number IPS: 00000001706; Note: Chip Res 1%; Artikkelnr Noca: N.A.
R41-R46 = R0201-1M0: as R4 on sheet pca20035_sheet2_nrf91_mcu
TP9 TP10 = TP_SMD_Ø1.5MM: as TP32 on sheet pca20035_sheet2_nrf91_mcu
U7 = ADXL372: Micropower, 3-Axis, ±200g digital output acelerometer; Manufacturer: Analog Devices; Part number IPS: 00000001798; Artikkelnr Noca: N.A.
U8 = ADXL362: Micropower, 3-Axis, ±2 g/±4 g/±8 g Digital Output MEMS Accelerometer; Manufacturer: Analog Devices; Part number IPS: 00000001799; Artikkelnr Noca: N.A.
U9 = BME680: Low power gas, pressure, temperature & humidity sensor; Manufacturer: Bosch; Part number IPS: 00000001800; Artikkelnr Noca: N.A.
U10 = BH1749NUC: Digital 16bit Serial Output Type Color Sensor IC; Manufacturer: Rohm Semiconductor; Part number IPS: 00000001801; Artikkelnr Noca: N.A.

## Sheet pca20035_sheet3_nrf52_mcu.SchDoc: Thingy:91 nRF52840 MCU
size A3; Organization: Nordic Semiconductor; DocumentNumber: 3; Revision: 1.0.0; SheetNumber: 3; SheetTotal: 6; Author: RUBR; CompanyName: Nordic Semiconductor; DrawnBy: RUBR; DocumentSize: A3
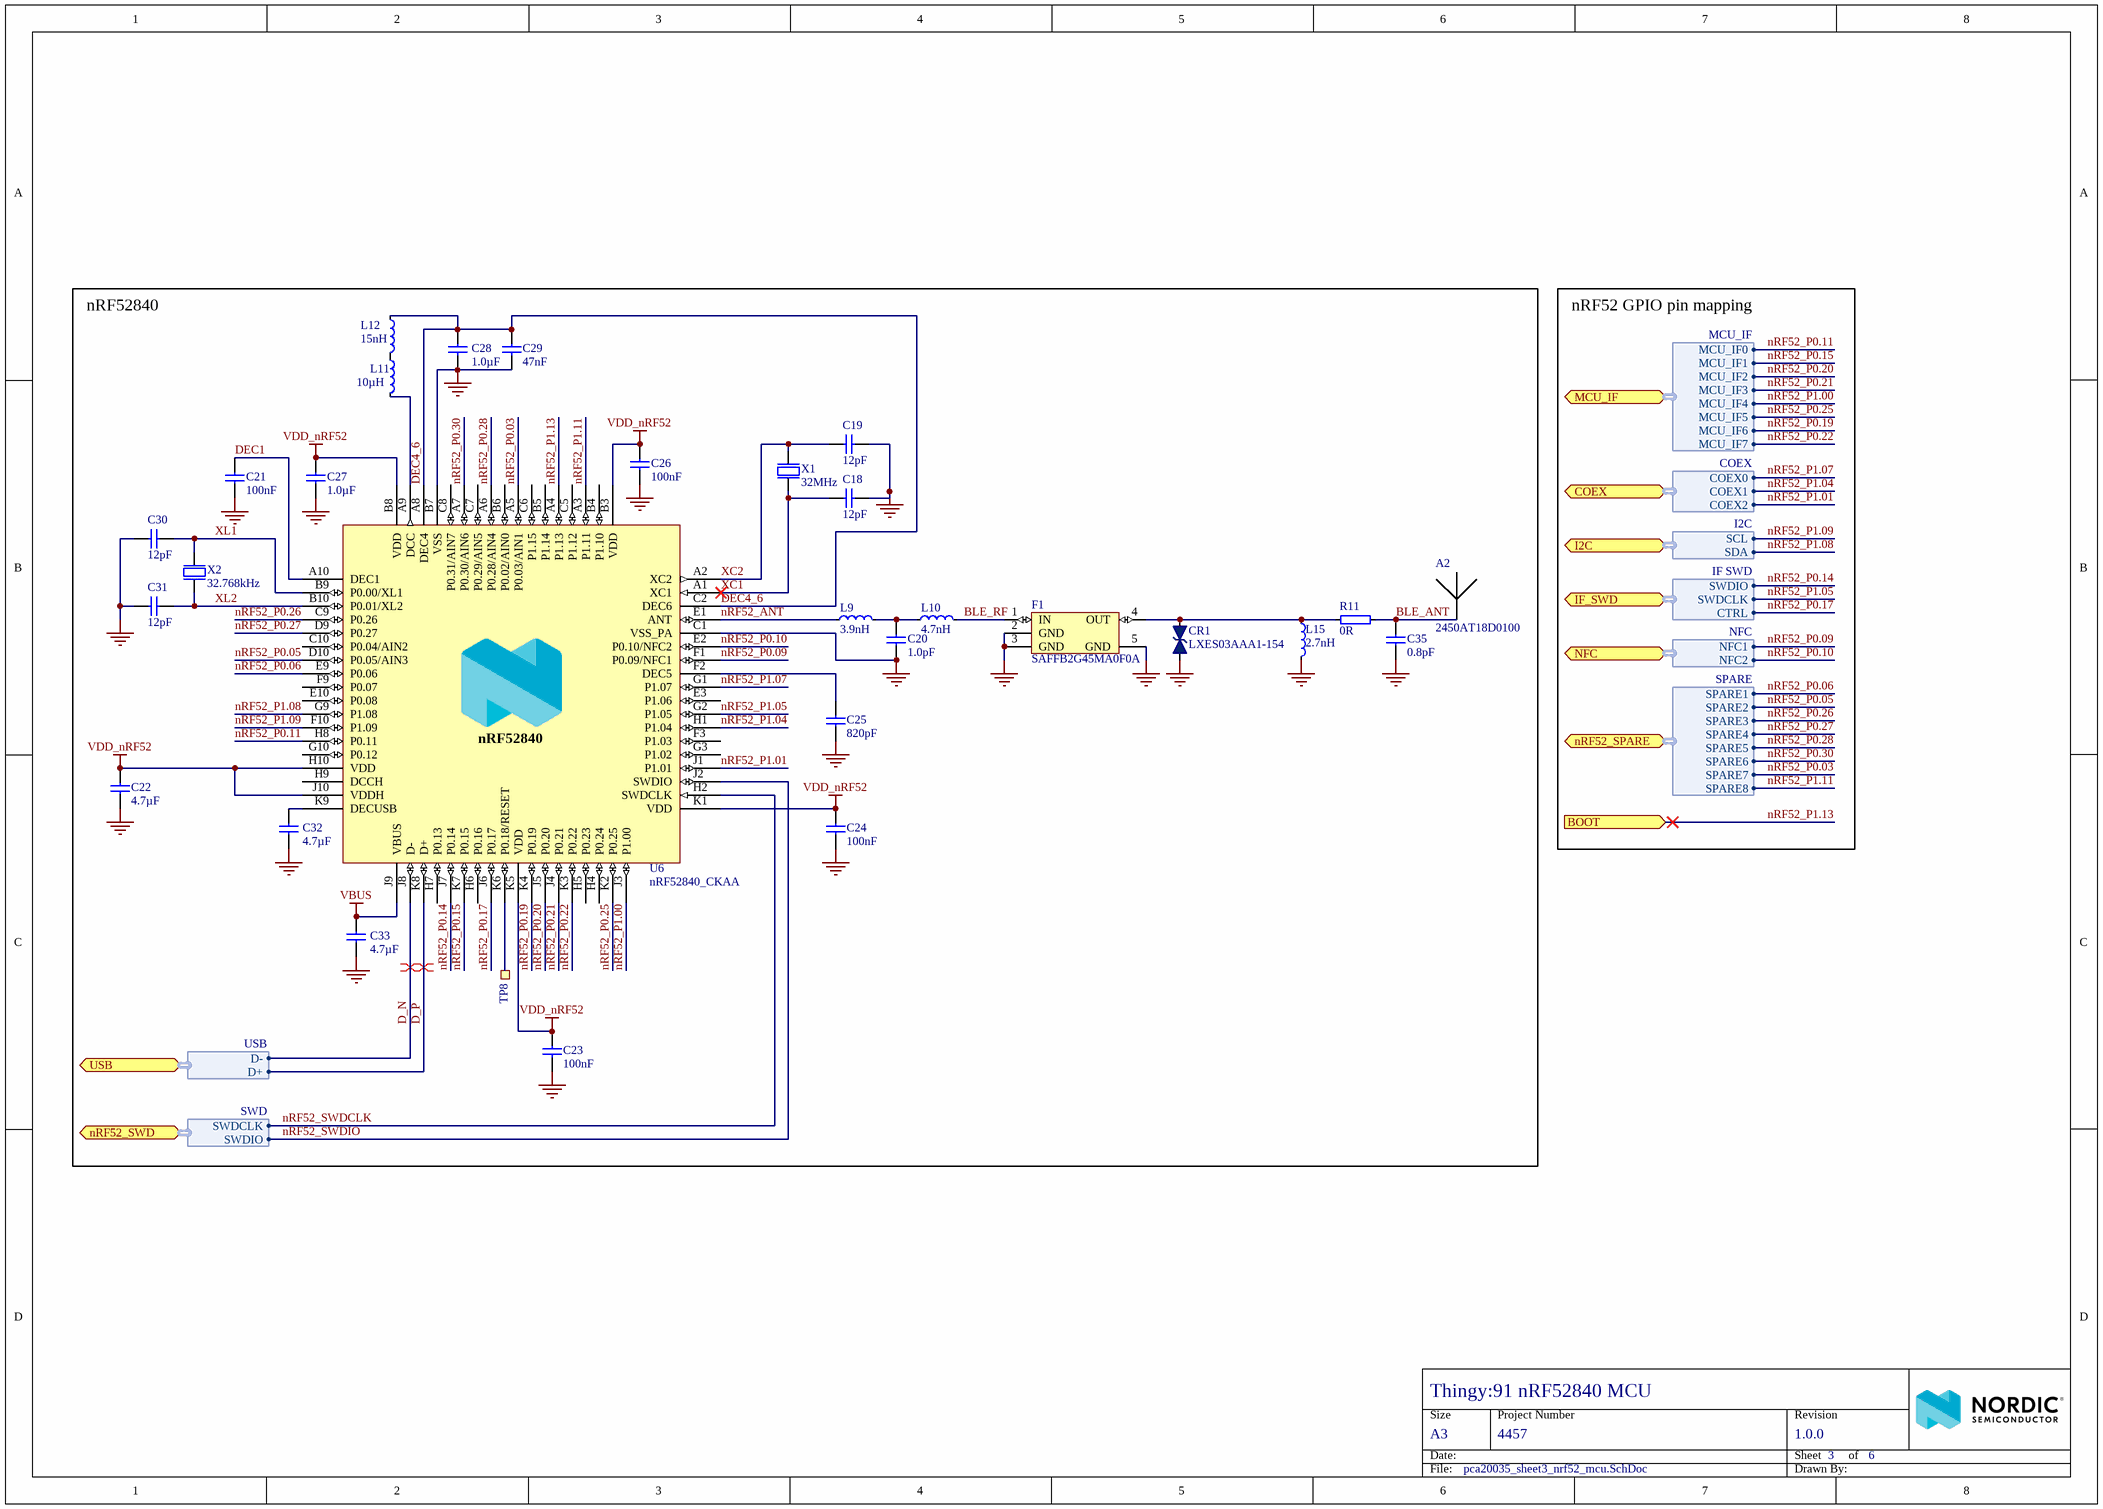
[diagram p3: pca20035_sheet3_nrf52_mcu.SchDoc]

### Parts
A2  2450AT18D0100  [2450AT18D0100_STD-R]
C18  12pF  [CAPC0603X03L_C]
C19  12pF  [CAPC0603X03L_C]
C20  1.0pF  [CAPC0603X03L_C]
C21  100nF  [CAPC0603X03L_C]
C22  4.7µF  [CAPC1608X06L]
C23  100nF  [CAPC0603X03L_C]
C24  100nF  [CAPC0603X03L_C]
C25  820pF  [CAPC0603X03L_C]
C26  100nF  [CAPC0603X03L_C]
C27  1.0µF  [CAPC1608X06L]
C28  1.0µF  [CAPC1608X06L]
C29  47nF  [CAPC0603X03L_C]
C30  12pF  [CAPC0603X03L_C]
C31  12pF  [CAPC0603X03L_C]
C32  4.7µF  [CAPC1608X06L]
C33  4.7µF  [CAPC1608X06L]
C35  0.8pF  [CAPC0603X03L_C]
CR1  LXES03AAA1-154  [LXES03AAA1-154]
F1  SAFFB2G45MA0F0A  [SAFFB2G45MA0F0A]
L9  3.9nH  [INDC0603X03L_C]
L10  4.7nH  [INDC0603X03L_C]
L11  10µH  [INDC1608X06L]
L12  15nH  [INDC1005X04L]
L15  2.7nH  [INDC0603X03L_C]
R11  0R  [RESC0603X03L_C]
TP8  Ø1.0mm,SMD  [TP_SMD_Ø1.0mm]  (value not drawn)  (no BOM)
U6  nRF52840_CKAA  [BGA94C35P10X10_352X356X50]
X1  32MHz  [BT-XTAL_2016]
X2  32.768kHz  [XTAL_1610]

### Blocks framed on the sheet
nRF52840: A2 C18-C33 C35 CR1 F1 L9-L12 L15 R11 TP8 U6 X1 X2

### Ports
BOOT (in), COEX (bidir, harness COEX), I2C (bidir, harness I2C), IF_SWD (bidir, harness IF SWD), MCU_IF (bidir, harness MCU_IF), NFC (bidir, harness NFC), nRF52_SPARE (bidir, harness SPARE), nRF52_SWD (bidir, harness SWD), USB (bidir, harness USB)

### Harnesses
SWD: SWDIO, SWDCLK
MCU_IF: MCU_IF0, MCU_IF1, MCU_IF2, MCU_IF3, MCU_IF4, MCU_IF5, MCU_IF6, MCU_IF7
I2C: SDA, SCL
COEX: COEX2, COEX1, COEX0
NFC: NFC2, NFC1
SPARE: SPARE1, SPARE2, SPARE3, SPARE4, SPARE5, SPARE6, SPARE7, SPARE8
IF SWD: SWDIO, SWDCLK, CTRL
USB: D-, D+

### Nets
GND: A2.2(GND) C18.2 C19.2 C20.1 C21.2 C22.2 C23.2 C24.2 C25.2 C26.2 C27.2 C28.1 C29.2 C30.2 C31.2 C32.2 C33.2 C35.2 CR1.1 F1.2(GND) F1.3(GND) F1.5(GND) L15.2 U6.B7(VSS) U6.C1(VSS_PA) U6.C4(GND) U6.D3(GND) U6.D4(GND) U6.D5(GND) U6.D6(GND) U6.D7(GND) U6.D8(GND) U6.E4(GND) U6.E5(GND) U6.E6(GND) U6.E7(GND) U6.E8(GND) U6.F4(GND) U6.F5(GND) U6.F6(GND) U6.F7(GND) U6.F8(GND) U6.G4(GND) U6.G5(GND) U6.G6(GND) U6.G7(GND) U6.G8(GND) U6.K10(GND) X1.2(GND) X1.4(GND)
VBUS: C33.1 U6.J9(VBUS)
VDD_nRF52: C22.1 C23.1 C24.1 C26.1 C27.1 U6.B3(VDD) U6.B8(VDD) U6.H10(VDD) U6.J10(VDDH) U6.K1(VDD) U6.K5(VDD)
BLE_ANT: A2.1 C35.1 R11.2
BLE_RF: F1.1(IN) L10.2
D_N: U6.J8(D-) ; port USB.D-
D_P: U6.K8(D+) ; port USB.D+
DEC1: C21.1 U6.A10(DEC1)
DEC4_6: C28.2 C29.1 L12.1 U6.A8(DEC4) U6.C2(DEC6)
nRF52_ANT: L9.1 U6.E1(ANT)
nRF52_P0.03: U6.A5(P0.03/AIN1) ; port nRF52_SPARE.SPARE7
nRF52_P0.05: U6.D10(P0.05/AIN3) ; port nRF52_SPARE.SPARE2
nRF52_P0.06: U6.E9(P0.06) ; port nRF52_SPARE.SPARE1
nRF52_P0.09: U6.F1(P0.09/NFC1) ; port NFC.NFC1
nRF52_P0.10: U6.E2(P0.10/NFC2) ; port NFC.NFC2
nRF52_P0.11: U6.H8(P0.11) ; port MCU_IF.MCU_IF0
nRF52_P0.14: U6.J7(P0.14) ; port IF_SWD.SWDIO
nRF52_P0.15: U6.K7(P0.15) ; port MCU_IF.MCU_IF1
nRF52_P0.17: U6.J6(P0.17) ; port IF_SWD.CTRL
nRF52_P0.19: U6.K4(P0.19) ; port MCU_IF.MCU_IF6
nRF52_P0.20: U6.J5(P0.20) ; port MCU_IF.MCU_IF2
nRF52_P0.21: U6.J4(P0.21) ; port MCU_IF.MCU_IF3
nRF52_P0.22: U6.K3(P0.22) ; port MCU_IF.MCU_IF7
nRF52_P0.25: U6.K2(P0.25) ; port MCU_IF.MCU_IF5
nRF52_P0.26: U6.C9(P0.26) ; port nRF52_SPARE.SPARE3
nRF52_P0.27: U6.D9(P0.27) ; port nRF52_SPARE.SPARE4
nRF52_P0.28: U6.A6(P0.28/AIN4) ; port nRF52_SPARE.SPARE5
nRF52_P0.30: U6.A7(P0.30/AIN6) ; port nRF52_SPARE.SPARE6
nRF52_P1.00: U6.J3(P1.00) ; port MCU_IF.MCU_IF4
nRF52_P1.01: U6.J1(P1.01) ; port COEX.COEX2
nRF52_P1.04: U6.H1(P1.04) ; port COEX.COEX1
nRF52_P1.05: U6.G2(P1.05) ; port IF_SWD.SWDCLK
nRF52_P1.07: U6.G1(P1.07) ; port COEX.COEX0
nRF52_P1.08: U6.G9(P1.08) ; port I2C.SDA
nRF52_P1.09: U6.F10(P1.09) ; port I2C.SCL
nRF52_P1.11: U6.A3(P1.11) ; port nRF52_SPARE.SPARE8
nRF52_P1.13: U6.A4(P1.13) ; port BOOT
nRF52_SWDCLK: U6.H2(SWDCLK) ; port nRF52_SWD.SWDCLK
nRF52_SWDIO: U6.J2(SWDIO) ; port nRF52_SWD.SWDIO
XC1: C18.1 U6.A1(XC1) X1.1(inp)
XC2: C19.1 U6.A2(XC2) X1.3(out)
XL1: C30.1 U6.B9(P0.00/XL1) X2.1(inp)
XL2: C31.1 U6.B10(P0.01/XL2) X2.2(out)
NetC20_2: C20.2 L9.2 L10.1
NetC25_1: C25.1 U6.F2(DEC5)
NetC32_1: C32.1 U6.K9(DECUSB)
NetCR1_2: CR1.2 F1.4(OUT) L15.1 R11.1
NetL11_1: L11.1 L12.2
NetL11_2: L11.2 U6.A9(DCC)
NetTP8_1: TP8.1 U6.K6(P0.18/RESET)

Not connected (* = marked no-connect by the designer): U6 B4(P1.10) B5(P1.14) B6(P0.02/AIN0) C5(P1.12) C6(P1.15) C7(P0.29/AIN5) C8(P0.31/AIN7) C10(P0.04/AIN2) E3(P1.06) E10(P0.08) F3(P1.03) F9(P0.07) G3(P1.02) G10(P0.12) H4(P0.24) H5(P0.23) H6(P0.16) H7(P0.13) H9(DCCH)

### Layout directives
differential pair: D_N, D_P

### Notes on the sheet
- nRF52 GPIO pin mapping

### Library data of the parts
A2 = Johanson 2450AT18D0100_STD-R: 2.45 GHz chip antenna; Manufacturer: Johanson Technology; Part number IPS: 00000001415; Artikkelnr Noca: 53059035
C18 C19 C30 C31 = C0201-12p: Capacitor, NP0, ±2%; Part number IPS: 00000007848; Note: 25V; Artikkelnr Noca: N.A.
C20 = C0201-1.0p: Capacitor, NP0, ±0.05pF, 50V; Part number IPS: 00000001247; Artikkelnr Noca: N.A.
C21 C23 C24 C26 = C0201-100n: as C6 on sheet pca20035_sheet2_nrf91_mcu
C22 C32 = C0603-4µ7-6.3V-X7R: Capacitor, X7R, ±10%, 6.3V; Manufacturer: Samsung; Manufacturer Part Number: CL10B475KQ8NQNC; Part number IPS: 00000002541; Artikkelnr Noca: 20039473
C25 = C0201-820p: Capacitor, X7R, ±10%; Part number IPS: 00000001249; Note: 25V; Artikkelnr Noca: N.A.
C27 C28 = C0603-1µ0: Capacitor, X7R, ±10%; Part number IPS: 00000000616; Note: 16V; Artikkelnr Noca: 20039282
C29 = C0201-47n: Capacitor, X5R, ±10%; Part number IPS: 00000001250; Note: 10V; Artikkelnr Noca: N.A.
C33 = C0603-4µ7-10V-X7S: Capacitor, X7S, ±10%, 10V; Part number IPS: 00000001779; Artikkelnr Noca: 20030013
C35 = C0201-0.8p: Capacitor, NP0, ±0.05pF, 50V; Manufacturer: Murata; Manufacturer Part Number: GJM0335C1HR80WB01; Artikkelnr Noca: N.A.
CR1 = LXES03AAA1-154: TVS DIODE 4V 0201; Manufacturer: Murata; Part number IPS: 00000001782; Artikkelnr Noca: N.A.
F1 = SAFFB2G45MA0F0A: 2.4 GHz BPF; Manufacturer: MuRata; Part number IPS: 00000001784; Artikkelnr Noca: N.A.
L9 = L0201-3n9: Inductor, 400mA, ±0.1nH; Manufacturer: Murata; Manufacturer Part Number: LQP03TN3N9B02D; Part number IPS: 00000001253; Artikkelnr Noca: N.A.
L10 = L0201-4n7: Inductor, 350mA, ±3%; Manufacturer: Murata; Manufacturer Part Number: LQP03TN4N7H02D; Part number IPS: 00000001792; Artikkelnr Noca: N.A.
L11 = L0603-10µ: Inductor, 80mA, ±10%; Manufacturer: Taiyo Yuden; Manufacturer Part Number: LBMF1608T100K; Part number IPS: 00000007794; Note: LBMF1608T100K 10µH 80mA 0603; Artikkelnr Noca: 33029314
L12 = L0402-15n: Inductor, 320mA, ±5%; Manufacturer: Taiyo Yuden; Manufacturer Part Number: HK100515NJ-T; Part number IPS: 00000001262; Note: High frequency chip inductor ±10%; Artikkelnr Noca: 33029323
L15 = L0201-2n7-HQ-Murata: Inductor, 600mA, ±0.1ｎH, 120mOhm; Manufacturer: Murata; Manufacturer Part Number: LQP03HQ2N7B02; Note: -55°C ~ 125°C; Artikkelnr Noca: N.A.
R11 = R0201-0R: as R9 on sheet pca20035_sheet2_nrf91_mcu
TP8 = TP_SMD_Ø1.0MM: as TP1 on sheet pca20035_sheet2_nrf91_mcu
U6 = nRF52840-CKAAD0: Multi-protocol Bluetooth Low Energy, IEEE 802.15.4, ANT and 2.4GHz proprietary system-on-chip; Manufacturer: Nordic Semiconductor; Part number IPS: 80000001822; Artikkelnr Noca: N.A.
X1 = XTAL_SMD2016_32MHz_8pF_Golledge: XTAL SMD 2016, 32MHz, Cl=8pF, Tol: ±10ppm, Stab: ±15ppm; Manufacturer Part Number: MP06003; Part number IPS: 00000001431; Note: XTAL SMD 32.000MHz; Artikkelnr Noca: 22010050
X2 = XTAL_SMD1610_32.768kHz_9pF_Seiko: XTAL SMD 1610, 32.768kHz, 9pF, ±20ppm; Manufacturer: Seiko; Manufacturer Part Number: SC16S-9.0PF20PPM; Part number IPS: 00000001802; Note: XTAL SMD 32.768kHz; Artikkelnr Noca: N.A.

## Sheet pca20035_sheet6_interface.SchDoc: Thingy:91 Interface
size A3; Organization: Nordic Semiconductor; DocumentNumber: 6; Revision: 1.0.0; SheetNumber: 6; SheetTotal: 6; Author: RUBR; CompanyName: Nordic Semiconductor; DrawnBy: RUBR; DocumentSize: A3
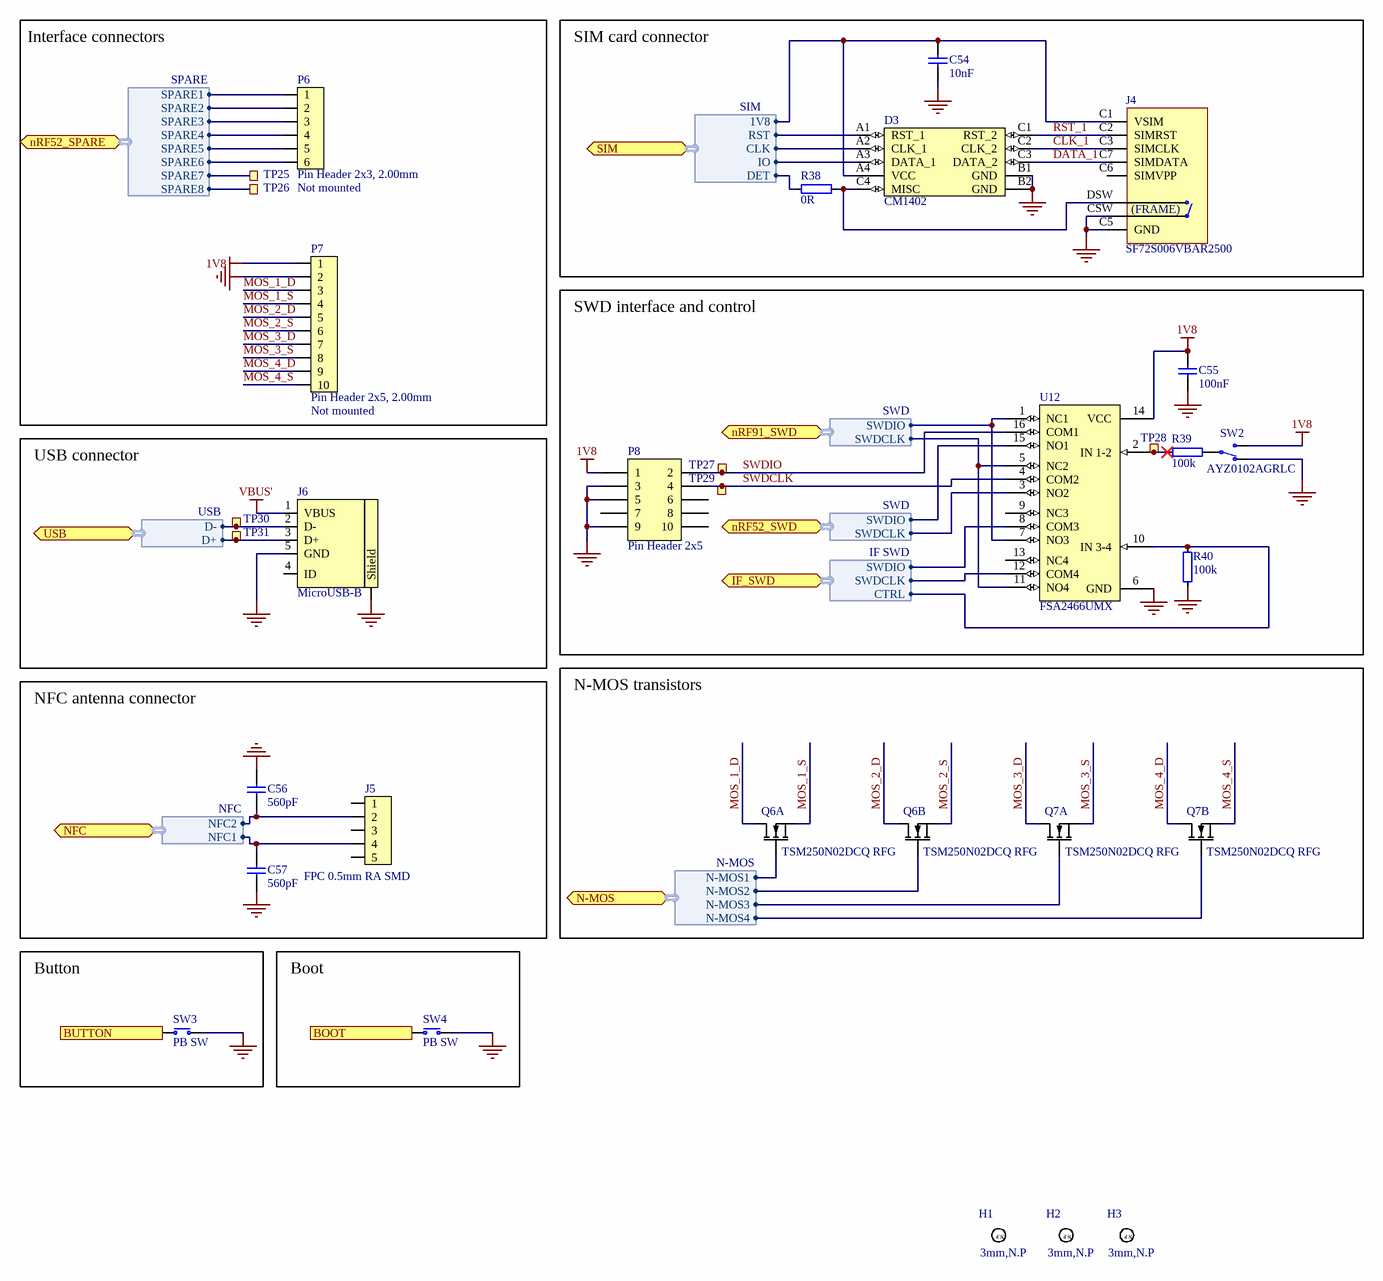
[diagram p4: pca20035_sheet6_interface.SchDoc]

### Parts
C54  10nF  [CAPC0603X03L_C]
C55  100nF  [CAPC0603X03L_C]
C56  560pF  [CAPC0603X03L_C]
C57  560pF  [CAPC0603X03L_C]
D3  CM1402  [CM1402]
H1  3mm,N.P  [HOLE_NP_3MM]  (no BOM)
H2  3mm,N.P  [HOLE_NP_3MM]  (no BOM)
H3  3mm,N.P  [HOLE_NP_3MM]  (no BOM)
J4  SF72S006VBAR2500  [SF72S006VBAR2500]
J5  FPC 0.5mm RA SMD  [FPC_05P-0.5mm-RA-SMD]
J6  MicroUSB-B  [USB-Micro-B-RA-SMD-PiP]
P6  Pin Header 2x3, 2.00mm  Assembly: Not mounted  [HDR_2x3_TH_2.00MM-NC]
P7  Pin Header 2x5, 2.00mm  Assembly: Not mounted  [HDR_2x5_TH_2.00MM-NC]
P8  Pin Header 2x5  [HDR_2x5-SMD-1.27mm-ANG]
Q6  TSM250N02DCQ RFG  [DFN65P200X200X80_HS-6N]  (parts A,B of 2)
Q7  TSM250N02DCQ RFG  [DFN65P200X200X80_HS-6N]  (parts A,B of 2)
R38  0R  [RESC0603X03L_C]
R39  100k  [RESC0603X03L_C]
R40  100k  [RESC0603X03L_C]
SW2  AYZ0102AGRLC  [AYZ0102AGRLC]
SW3  PB SW  [Switch-PB-6.2x6.3mm-SMD]
SW4  PB SW  [SW_TACTILE_2.6x3.0MM_4-LEAD]
TP25  Ø1.0mm,SMD  [TP_SMD_Ø1.0mm]  (value not drawn)  (no BOM)
TP26  Ø1.0mm,SMD  [TP_SMD_Ø1.0mm]  (value not drawn)  (no BOM)
TP27  Ø1.5mm,SMD  [TP_SMD_Ø1.5mm]  (value not drawn)  (no BOM)
TP28  Ø1.5mm,SMD  [TP_SMD_Ø1.5mm]  (value not drawn)  (no BOM)
TP29  Ø1.5mm,SMD  [TP_SMD_Ø1.5mm]  (value not drawn)  (no BOM)
TP30  Ø1.5mm,SMD  [TP_SMD_Ø1.5mm]  (value not drawn)  (no BOM)
TP31  Ø1.5mm,SMD  [TP_SMD_Ø1.5mm]  (value not drawn)  (no BOM)
U12  FSA2466UMX  [XQFN40P180X260X50-16N]

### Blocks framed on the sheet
Interface connectors: P6 P7 TP25 TP26
SIM card connector: C54 D3 J4 R38
SWD interface and control: C55 P8 R39 R40 SW2 TP27-TP29 U12
USB connector: J6 TP30 TP31
NFC antenna connector: C56 C57 J5
N-MOS transistors: Q6 Q7
Button: SW3
Boot: SW4

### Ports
BOOT (out), BUTTON (out), IF_SWD (bidir, harness IF SWD), N-MOS (bidir, harness N-MOS), NFC (bidir, harness NFC), nRF52_SPARE (bidir, harness SPARE), nRF52_SWD (bidir, harness SWD), nRF91_SWD (bidir, harness SWD), SIM (bidir, harness SIM), USB (bidir, harness USB)

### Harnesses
SWD: SWDIO, SWDCLK
IF SWD: SWDIO, SWDCLK, CTRL
SIM: DET, RST, CLK, IO, 1V8
NFC: NFC2, NFC1
N-MOS: N-MOS1, N-MOS2, N-MOS3, N-MOS4
SPARE: SPARE1, SPARE2, SPARE3, SPARE4, SPARE5, SPARE6, SPARE7, SPARE8
USB: D-, D+

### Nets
1V8: C55.1 P7.1 P8.1 SW2.3(N.O) U12.14(VCC)
GND: C54.2 C55.2 C56.2 C57.1 D3.B1(GND) D3.B2(GND) J4.0(GND) J4.C5(GND) J4.CSW J6.5(GND) J6.6(Shield) P7.2 P8.3 P8.5 P8.9 R40.2 SW2.1(N.C) SW3.1(N.O) SW4.1(N.O) U12.6(GND)
VBUS': J6.1(VBUS)
CLK_1: D3.C2(CLK_2) J4.C3(SIMCLK)
D_N: J6.2(D-) TP30.1 ; port USB.D-
D_P: J6.3(D+) TP31.1 ; port USB.D+
DATA_1: D3.C3(DATA_2) J4.C7(SIMDATA)
MOS_1_D: P7.3 Q6.6(D1)
MOS_1_S: P7.4 Q6.1(S1)
MOS_2_D: P7.5 Q6.3(D2)
MOS_2_S: P7.6 Q6.4(S2)
MOS_3_D: P7.7 Q7.6(D1)
MOS_3_S: P7.8 Q7.1(S1)
MOS_4_D: P7.9 Q7.3(D2)
MOS_4_S: P7.10 Q7.4(S2)
nRF52_P0.03: TP25.1 ; port nRF52_SPARE.SPARE7
nRF52_P0.05: P6.2 ; port nRF52_SPARE.SPARE2
nRF52_P0.06: P6.1 ; port nRF52_SPARE.SPARE1
nRF52_P0.09: C57.2 J5.4 ; port NFC.NFC1
nRF52_P0.10: C56.1 J5.2 ; port NFC.NFC2
nRF52_P0.14: U12.8(COM3) ; port IF_SWD.SWDIO
nRF52_P0.17: R40.1 U12.10(IN_3-4) ; port IF_SWD.CTRL
nRF52_P0.26: P6.3 ; port nRF52_SPARE.SPARE3
nRF52_P0.27: P6.4 ; port nRF52_SPARE.SPARE4
nRF52_P0.28: P6.5 ; port nRF52_SPARE.SPARE5
nRF52_P0.30: P6.6 ; port nRF52_SPARE.SPARE6
nRF52_P1.05: U12.12(COM4) ; port IF_SWD.SWDCLK
nRF52_P1.11: TP26.1 ; port nRF52_SPARE.SPARE8
nRF52_P1.13: SW4.2(COM) ; port BOOT
nRF52_SWDCLK: U12.3(NO2) ; port nRF52_SWD.SWDCLK
nRF52_SWDIO: U12.15(NO1) ; port nRF52_SWD.SWDIO
nRF91_SWDCLK: U12.5(NC2) U12.11(NO4) ; port nRF91_SWD.SWDCLK
nRF91_SWDIO: U12.1(NC1) U12.7(NO3) ; port nRF91_SWD.SWDIO
P0.13/AIN0: Q6.2(G1) ; port N-MOS.N-MOS1
P0.14/AIN1: Q6.5(G2) ; port N-MOS.N-MOS2
P0.15/AIN2: Q7.2(G1) ; port N-MOS.N-MOS3
P0.16/AIN3: Q7.5(G2) ; port N-MOS.N-MOS4
P0.26: SW3.2(COM) ; port BUTTON
RST_1: D3.C1(RST_2) J4.C2(SIMRST)
SIM_1V8: C54.1 D3.A4(VCC) J4.C1(VSIM) ; port SIM.1V8
SIM_CLK: D3.A2(CLK_1) ; port SIM.CLK
SIM_DET: R38.2 ; port SIM.DET
SIM_IO: D3.A3(DATA_1) ; port SIM.IO
SIM_RST: D3.A1(RST_1) ; port SIM.RST
SWDCLK: P8.4 TP29.1 U12.4(COM2)
SWDIO: P8.2 TP27.1 U12.16(COM1)
NetD3_C4: D3.C4(MISC) J4.DSW R38.1
NetR39_1: R39.1 SW2.2(COM)
NetR39_2: R39.2 TP28.1 U12.2(IN_1-2)

Not connected (* = marked no-connect by the designer): H1 1; H2 1; H3 1; J4 C6(SIMVPP); J5 1 3 5; J6 4(ID); P8 6 7 8 10; U12 9(NC3) 13(NC4)

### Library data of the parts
C54 = C0201-10n: Capacitor, X7R, ±10%; Part number IPS: 00000003480; Note: 10V; Artikkelnr Noca: N.A.
C55 = C0201-100n: as C6 on sheet pca20035_sheet2_nrf91_mcu
C56 C57 = C0201-560p: Capacitor, NP0, ±5%, 25V; Artikkelnr Noca: N.A.
D3 = CM1402: EMI Network Filter Arrays SIM CARD EMI FILTER WITH ESD PROTECTION; Manufacturer: ON Semiconductor; Manufacturer Part Number: CM1402-03CP; Part number IPS: 00000009949; Artikkelnr Noca: N.A.
H1-H3 = Hole_3MM_NP: Regular Non-Plated, 3mm hole; Manufacturer: Nordic Semiconductor; Artikkelnr Noca: N.A.
J4 = SF72S006VBAR2500: n 8 (6 + 2) Position Card Connector NANO SIM Surface Mount, Right Angle Gold; Manufacturer: JAE; Part number IPS: 00000009956; Artikkelnr Noca: N.A.
J5 = FPC_05P-0.5mm-RA-SMD: 0.5mm FPC, 5P,Right Angle SMT,Double Contact,H=1.2mm,White, Tin plated; Manufacturer: W-CON; Manufacturer Part Number: 5141-05RZDNWR01; Part number IPS: 00000007792; Artikkelnr Noca: 55010020
J6 = USB-Micro-B-RA-SMD-PiP: MicroUSB-B-SMT; Manufacturer: Allen Creations Corp.; Manufacturer Part Number: AJU55-BS2111-L; Part number IPS: 00000007790; Artikkelnr Noca: 55029020
P6 = Pin Header 2x3 TH, 2.00mm, N.C.: Pin Header 2x3, TH, 2.00mm; Artikkelnr Noca: N.A.
P7 = Pin Header 2x5 TH, 2.00mm, N.C.: Pin Header 2x5, TH, 2.00mm; Artikkelnr Noca: N.A.
P8 = Pin Header 2x5 SMD, 1.27mm, Angled: Pin Header 2x5, 1.27mm (50mil); Manufacturer: Samtec; Manufacturer Part Number: FTSH-105-01-L-DH-A-C-TR; Part number IPS: 00000007800; Artikkelnr Noca: N.A.
Q6 Q7 = TSM250N02DCQ RFG: as Q2 on sheet pca20035_sheet4_sensors_and_leds
R38 = R0201-0R: as R9 on sheet pca20035_sheet2_nrf91_mcu
R39 R40 = R0201-100k: Resistor, ±1%, 0.05W; Part number IPS: 00000001419; Note: Chip Res 1%; Artikkelnr Noca: N.A.
SW2 = AYZ0102AGRLC: Miniature slide switch, SPDT, Right-Angle, ON-ON, 12V, 100mA; Manufacturer: C&K; Artikkelnr Noca: N.A.
SW3 = Switch-PB-6.2x6.3mm-SMD: Tactile Switch, SPNO, SMD, 160gf, 6.2x6.3x2.5mm; Manufacturer: Dailywell; Manufacturer Part Number: TS604VM1-025BR-R; Part number IPS: 00000007812; Artikkelnr Noca: 50019106
SW4 = KMT021 NGJ LHS: Nano-Miniature Top Actuated Tact Switch with extended life 3.0x2.6mm; Manufacturer: C & K; Artikkelnr Noca: N.A.
TP25 TP26 = TP_SMD_Ø1.0MM: as TP1 on sheet pca20035_sheet2_nrf91_mcu
TP27-TP31 = TP_SMD_Ø1.5MM: as TP32 on sheet pca20035_sheet2_nrf91_mcu
U12 = FSA2466UMX: Data / Audio Low-Voltage Dual DPDT Analog Switch; Manufacturer: Fairchild Semiconductor; Part number IPS: 00000009986; Artikkelnr Noca: 15070069

## Sheet pca20035_sheet5_power_supply.SchDoc: Thingy:91 Power Supply
size A3; Organization: Nordic Semiconductor; DocumentNumber: 5; Revision: 1.0.0; SheetNumber: 5; SheetTotal: 6; Author: RUBR; CompanyName: Nordic Semiconductor; DrawnBy: RUBR; DocumentSize: A3
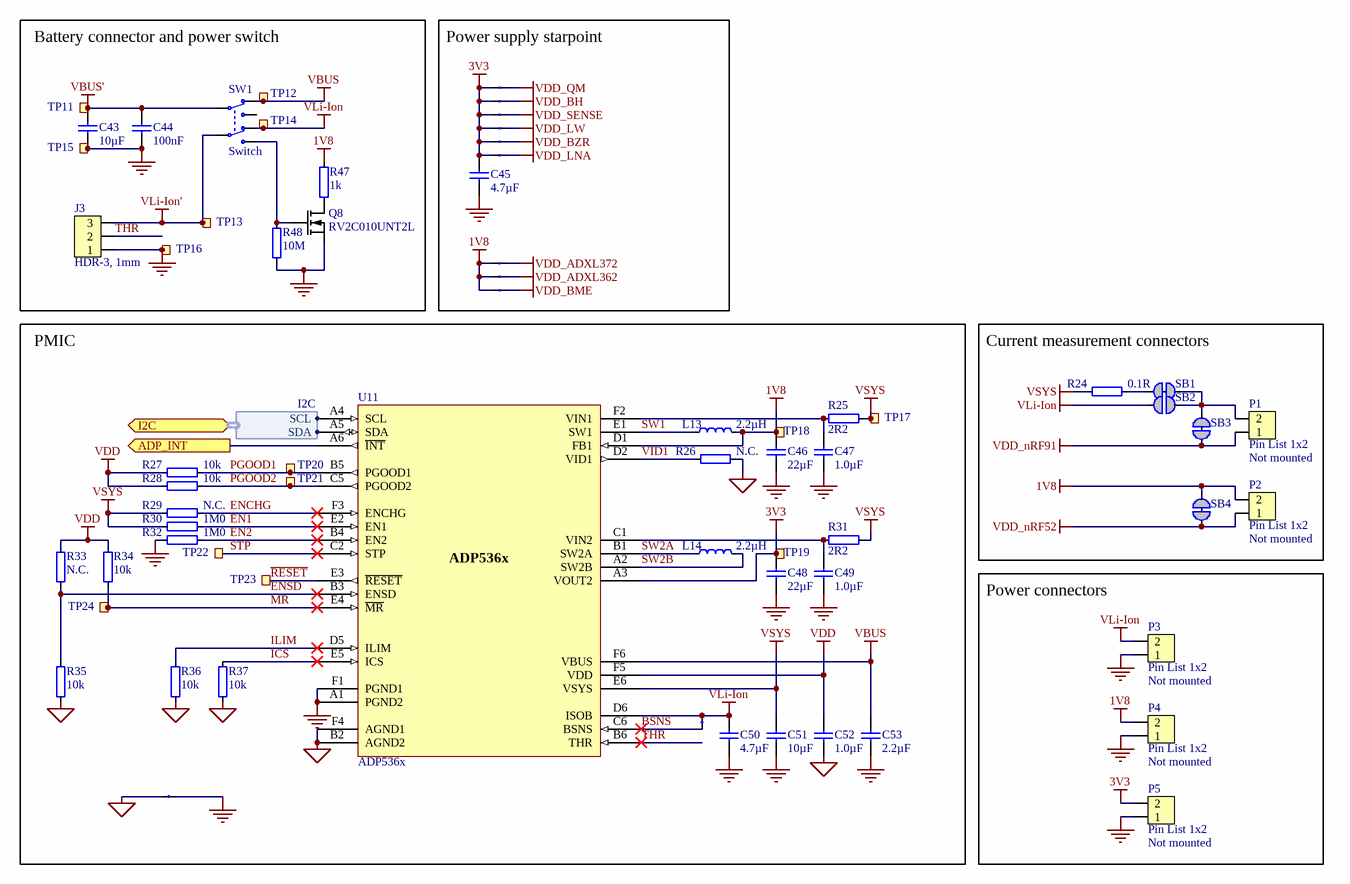
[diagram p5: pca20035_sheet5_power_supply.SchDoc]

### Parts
C43  10µF  [CAPC1608X06L]
C44  100nF  [CAPC0603X03L_C]
C45  4.7µF  [CAPC1608X06L]
C46  22µF  [CAPC1608X06L]
C47  1.0µF  [CAPC1005X04L]
C48  22µF  [CAPC1608X06L]
C49  1.0µF  [CAPC1608X06L]
C50  4.7µF  [CAPC1608X06L]
C51  10µF  [CAPC1608X06L]
C52  1.0µF  [CAPC1005X04L]
C53  2.2µF  [CAPC1608X06L]
J3  HDR-3, 1mm  [SM03B-SRSS-TB]
L13  2.2µH  [INDC2016X18N]
L14  2.2µH  [INDC2016X18N]
P1  Pin List 1x2  Assembly: Not mounted  [LIST_1x2-NC]
P2  Pin List 1x2  Assembly: Not mounted  [LIST_1x2-NC]
P3  Pin List 1x2  Assembly: Not mounted  [LIST_1x2-NC]
P4  Pin List 1x2  Assembly: Not mounted  [LIST_1x2-NC]
P5  Pin List 1x2  Assembly: Not mounted  [LIST_1x2-NC]
Q8  RV2C010UNT2L  [DFN65P100X40-3L]
R24  0.1R  [RESC1005X04L]
R25  2R2  [RESC1005X04L]
R26  N.C.  [RESC0603X03L_C]
R27  10k  [RESC0603X03L_C]
R28  10k  [RESC0603X03L_C]
R29  N.C.  [RESC0603X03L_C]
R30  1M0  [RESC0603X03L_C]
R31  2R2  [RESC1005X04L]
R32  1M0  [RESC0603X03L_C]
R33  N.C.  [RESC0603X03L_C]
R34  10k  [RESC0603X03L_C]
R35  10k  [RESC0603X03L_C]
R36  10k  [RESC0603X03L_C]
R37  10k  [RESC0603X03L_C]
R47  1k  [RESC0603X03L_C]
R48  10M  [RESC0603X03L_C]
SB1  Solderbridge  [Solderbridge_Shorted]  (value not drawn)  (net tie, no BOM)
SB2  Solderbridge  [Solderbridge]  (value not drawn)  (no BOM)
SB3  Solderbridge  [Solderbridge_Shorted]  (value not drawn)  (net tie, no BOM)
SB4  Solderbridge  [Solderbridge_Shorted]  (value not drawn)  (net tie, no BOM)
ST1  *  [2 PIN STARPOINT]  (value not drawn)  (net tie, no BOM)
ST2  *  [2 PIN STARPOINT]  (value not drawn)  (net tie, no BOM)
ST3  *  [2 PIN STARPOINT]  (value not drawn)  (net tie, no BOM)
ST4  *  [2 PIN STARPOINT]  (value not drawn)  (net tie, no BOM)
ST5  *  [2 PIN STARPOINT]  (value not drawn)  (net tie, no BOM)
ST6  *  [2 PIN STARPOINT]  (value not drawn)  (net tie, no BOM)
ST7  *  [2 PIN STARPOINT]  (value not drawn)  (net tie, no BOM)
ST8  *  [2 PIN STARPOINT]  (value not drawn)  (net tie, no BOM)
ST9  *  [2 PIN STARPOINT]  (value not drawn)  (net tie, no BOM)
ST10  *  [2 PIN STARPOINT]  (value not drawn)  (net tie, no BOM)
ST11  *  [2 PIN STARPOINT]  (value not drawn)  (net tie, no BOM)
SW1  Switch  [Switch-Slide-RA-J-Lead-DPDT-8.5x3.5mm]
TP11  Ø1.5mm,SMD  [TP_SMD_Ø1.5mm]  (value not drawn)  (no BOM)
TP12  Ø1.5mm,SMD  [TP_SMD_Ø1.5mm]  (value not drawn)  (no BOM)
TP13  Ø1.5mm,SMD  [TP_SMD_Ø1.5mm]  (value not drawn)  (no BOM)
TP14  Ø1.5mm,SMD  [TP_SMD_Ø1.5mm]  (value not drawn)  (no BOM)
TP15  Ø1.5mm,SMD  [TP_SMD_Ø1.5mm]  (value not drawn)  (no BOM)
TP16  Ø1.5mm,SMD  [TP_SMD_Ø1.5mm]  (value not drawn)  (no BOM)
TP17  Ø1.5mm,SMD  [TP_SMD_Ø1.5mm]  (value not drawn)  (no BOM)
TP18  Ø1.5mm,SMD  [TP_SMD_Ø1.5mm]  (value not drawn)  (no BOM)
TP19  Ø1.5mm,SMD  [TP_SMD_Ø1.5mm]  (value not drawn)  (no BOM)
TP20  Ø1.5mm,SMD  [TP_SMD_Ø1.5mm]  (value not drawn)  (no BOM)
TP21  Ø1.5mm,SMD  [TP_SMD_Ø1.5mm]  (value not drawn)  (no BOM)
TP22  Ø1.0mm,SMD  [TP_SMD_Ø1.0mm]  (value not drawn)  (no BOM)
TP23  Ø1.0mm,SMD  [TP_SMD_Ø1.0mm]  (value not drawn)  (no BOM)
TP24  Ø1.0mm,SMD  [TP_SMD_Ø1.0mm]  (value not drawn)  (no BOM)
U11  ADP536x  [BGA32C40P6X6_238X238X56]

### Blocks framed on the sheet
Battery connector and power switch: C43 C44 J3 Q8 R47 R48 SW1 TP11-TP16
Power supply starpoint: C45 ST1-ST9
PMIC: C46-C53 L13 L14 R25-R37 ST10 ST11 TP17-TP24 U11
Current measurement connectors: P1 P2 R24 SB1-SB4
Power connectors: P3-P5

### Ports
ADP_INT (out), I2C (bidir, harness I2C)

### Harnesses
I2C: SDA, SCL

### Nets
1V8: C46.2 L13.2 P2.2 P4.2 R47.1 SB4.2 ST7.1 ST8.1 ST9.1 TP18.1 U11.D1(FB1)
3V3: C45.2 C48.2 P5.2 ST1.1 ST2.1 ST3.1 ST4.1 ST5.1 ST6.1 TP19.1 U11.A3(VOUT2)
AGND: C52.1 R26.2 R35.1 R36.2 R37.2 ST11.1 U11.B2(AGND2) U11.F4(AGND1)
GND: C43.2 C44.2 C45.1 C46.1 C47.1 C48.1 C49.1 C50.1 C51.1 C53.1 J3.1 P3.1 P4.1 P5.1 Q8.2(S) R32.1 R48.2 ST11.2 TP15.1 TP16.1 U11.A1(PGND2) U11.F1(PGND1)
VBUS: C53.2 SW1.3(N.C-1) TP12.1 U11.F6(VBUS)
VBUS': C43.1 C44.1 SW1.2(COM-1) TP11.1
VDD: C52.2 R27.1 R28.1 R33.2 R34.1 U11.F5(VDD)
VDD_ADXL362: ST8.2
VDD_ADXL372: ST7.2
VDD_BH: ST2.2
VDD_BME: ST9.2
VDD_BZR: ST5.2
VDD_LNA: ST6.2
VDD_LW: ST4.2
VDD_nRF52: P2.1 SB4.1
VDD_nRF91: P1.1 SB3.1
VDD_QM: ST1.2
VDD_SENSE: ST3.2
VLi-Ion: C50.2 P3.2 SB2.2 ST10.2 SW1.6(N.C-2) TP14.1 U11.D6(ISOB)
VLi-Ion': J3.3 SW1.5(COM-2) TP13.1
VSYS: C51.2 R24.2 R25.2 R29.1 R30.1 R31.2 TP17.1 U11.E6(VSYS)
BSNS: ST10.1 U11.C6(BSNS)
EN1: R30.2 U11.E2(EN1)
EN2: R32.2 U11.B4(EN2)
ENCHG: R29.2 U11.F3(ENCHG)
ENSD: R33.1 R35.2 U11.B3(ENSD)
ICS: R37.1 U11.E5(ICS)
ILIM: R36.1 U11.D5(ILIM)
~{MR}: R34.2 TP24.1 U11.E4(~{MR})
nRF52_P1.08: U11.A5(SDA) ; port I2C.SDA
nRF52_P1.09: U11.A4(SCL) ; port I2C.SCL
P0.17/AIN4: U11.A6(~{INT}) ; port ADP_INT
PGOOD1: R27.2 TP20.1 U11.B5(PGOOD1)
PGOOD2: R28.2 TP21.1 U11.C5(PGOOD2)
~{RESET}: TP23.1 U11.E3(~{RESET})
STP: TP22.1 U11.C2(STP)
SW1: L13.1 U11.E1(SW1)
SW2A: L14.1 U11.B1(SW2A)
SW2B: L14.2 U11.A2(SW2B)
THR: J3.2 U11.B6(THR)
VID1: R26.1 U11.D2(VID1)
NetC47_2: C47.2 R25.1 U11.F2(VIN1)
NetC49_2: C49.2 R31.1 U11.C1(VIN2)
NetP1_2: P1.2 SB1.1 SB2.1 SB3.2
NetQ8_1: Q8.1(G) R48.1 SW1.4(N.O-2)
NetQ8_3: Q8.3(D) R47.2
NetR24_1: R24.1 SB1.2

Not connected (* = marked no-connect by the designer): SW1 1(N.O-1)

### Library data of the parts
C43 C51 = C0603-10µ: Capacitor, X5R, ±20%; Part number IPS: 00000007785; Note: 6.3V; Artikkelnr Noca: 20039234
C44 = C0201-100n: as C6 on sheet pca20035_sheet2_nrf91_mcu
C45 C50 = C0603-4µ7: as C1 on sheet pca20035_sheet2_nrf91_mcu
C46 C48 = C0603-22µ-6.3V: CAP CER 22UF 6.3V 20% X5R 0603; Manufacturer: Samsung; Manufacturer Part Number: CL10A226MQ8NRNC; Part number IPS: 00000007787; Artikkelnr Noca: N.A.
C47 C52 = C0402-1µ0: Capacitor, X5R, ±5%; Part number IPS: 00000007786; Note: 6.3V; Artikkelnr Noca: 20039235
C49 = C0603-1µ0: as C27 on sheet pca20035_sheet3_nrf52_mcu
C53 = C0603-2µ2-10V: Capacitor, X7R, ±10%, 10V; Manufacturer: Samsung; Manufacturer Part Number: CL10B225KP8NNNC; Part number IPS: 00000001781; Artikkelnr Noca: 20030083
J3 = SM03B-SRSS-TB: 1.0mm pitch connector side entry SMD; Manufacturer: JST; Manufacturer Part Number: SM03B-SRSS-TB(LF)(SN); Part number IPS: 00000001785; Note: JST, Header; Artikkelnr Noca: N.A.
L13 L14 = L0806-2µ2-1.2A-110mOhm: Shielded Multilayer Inductor, 1.2A, ±20%, 110mOhm, Q=10 @ 1MHz; Manufacturer: Wurth Electronics; Manufacturer Part Number: 74479776222A; Part number IPS: 80000001820; Artikkelnr Noca: N.A.
P1-P5 = Pin List 1x2, N.C.: Pin List 1x2, 2.54mm (100mil); Artikkelnr Noca: N.A.
Q8 = RV2C010UNT2L: N-Channel MOSFET, 20V, 1A, 470mOhm, 400mW; Manufacturer: Rohm Semiconductor; Part number IPS: N.A.; Artikkelnr Noca: 35010020
R24 = R0402-0R1: Resistor, ±1%, 0.063W; Part number IPS: 00000001795; Note: Chip Res 1%; Artikkelnr Noca: N.A.
R25 R31 = R0402-2R2: Resistor, ±1%, 0.063W; Part number IPS: 00000001796; Note: Chip Res 1%; Artikkelnr Noca: 27049009
R26 R29 R33 = R0201-N.C.: Not mounted; Note: Chip Res; Artikkelnr Noca: N.A.; Assembly: Not mounted
R27 R28 R34-R37 = R0201-10k: Resistor, ±1%, 0.05W; Part number IPS: 00000001255; Note: Chip Res 1%; Artikkelnr Noca: N.A.
R30 R32 = R0201-1M0: as R4 on sheet pca20035_sheet2_nrf91_mcu
R47 = R0201-1k0: as R1 on sheet pca20035_sheet2_nrf91_mcu
R48 = R0201-10M: Resistor, ±1%, 0.05W; Part number IPS: 00000001426; Note: Chip Res 1%; Artikkelnr Noca: N.A.
SB1 SB3 SB4 = Solderbridge Shorted: as SB7 on sheet pca20035_sheet2_nrf91_mcu
SB2 = Solderbridge: Artikkelnr Noca: N.A.
ST1-ST11 = 2 pin starpoint: Starpoint; Part number IPS: N.A.
SW1 = Switch-Slide-RA-J-Lead-DPDT-8.5x3.5mm_Copal: SMD slide Switch (ON-ON); Manufacturer: Copal Electronics Inc; Manufacturer Part Number: CL-SB-22A-11T; Part number IPS: 00000007811; Artikkelnr Noca: N.A.
TP11-TP21 = TP_SMD_Ø1.5MM: as TP32 on sheet pca20035_sheet2_nrf91_mcu
TP22-TP24 = TP_SMD_Ø1.0MM: as TP1 on sheet pca20035_sheet2_nrf91_mcu
U11 = ADP536x: Advanced Battery Management PMIC With Ultralow Iq Buck and Buck-Boost; Manufacturer: Analog Devices; Part number IPS: 80000001823; Artikkelnr Noca: N.A.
